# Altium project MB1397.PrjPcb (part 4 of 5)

## Sheet Peripherals.SchDoc: Peripherals
size A4; Date: Not used; ApprovedBy: Not used; CheckedBy: Not used; Author: Not used; CompanyName: STMicroelectronics; DrawnBy: Not used; Engineer: Not used; Organization: Not used; Address1: Not used; Address2: Not used; Address3: Not used; Address4: Not used; DocumentNumber: Not used; Revision: Not used; SheetNumber: 14; SheetTotal: 22
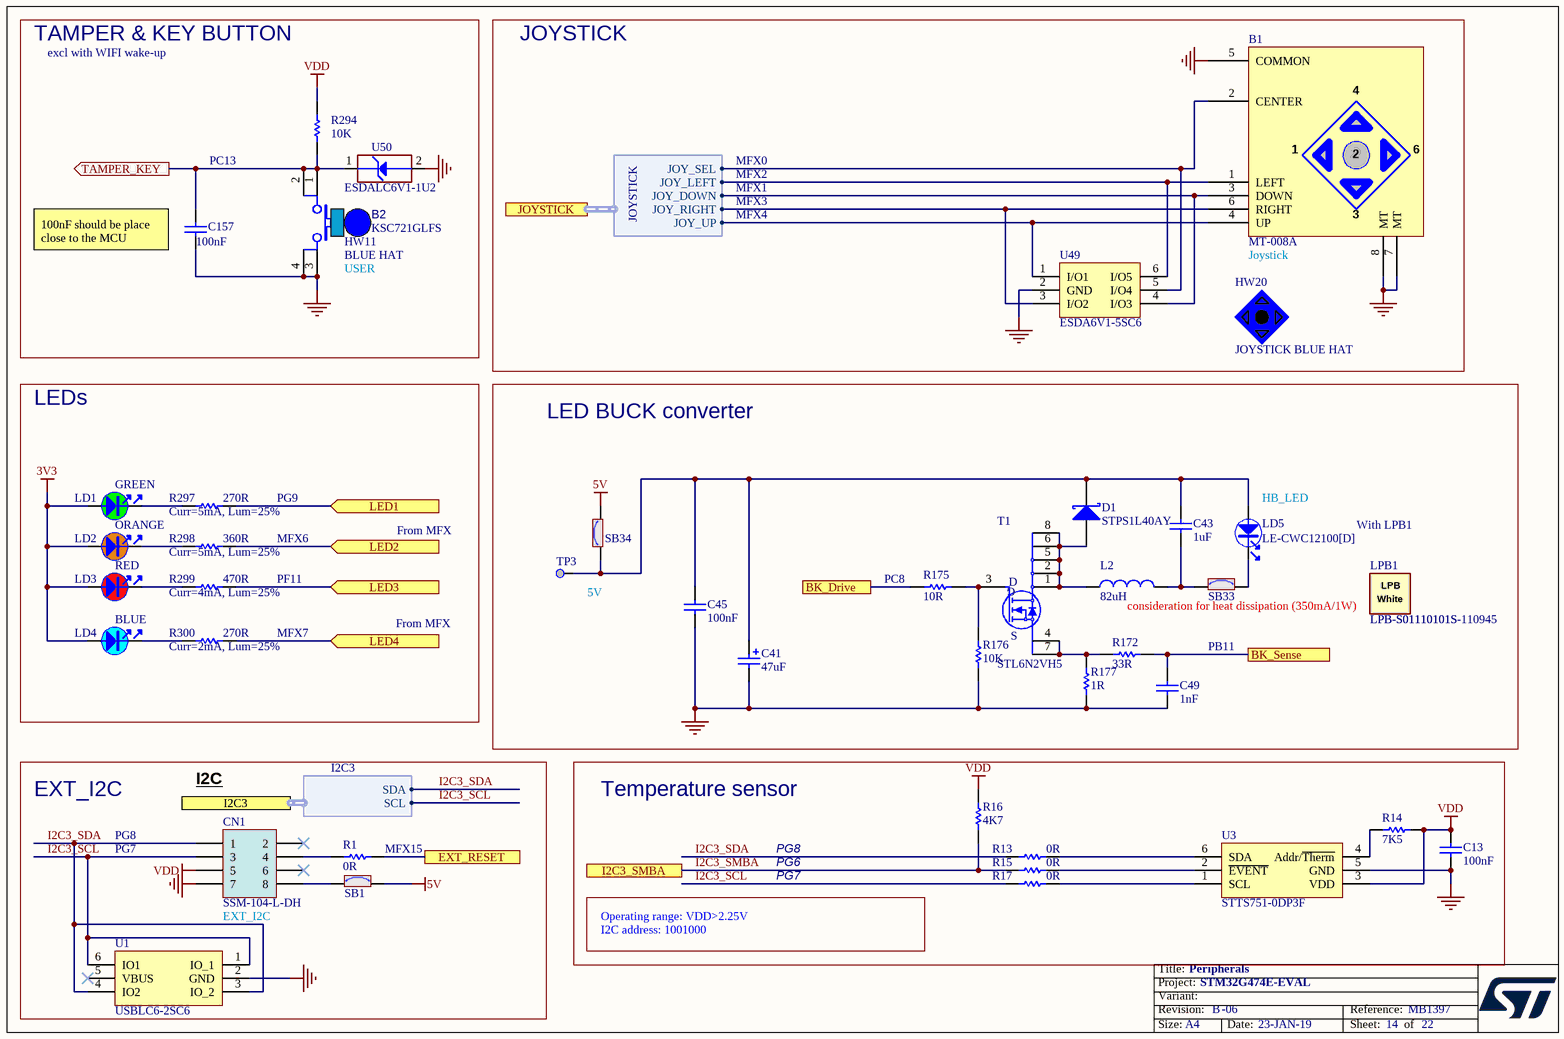
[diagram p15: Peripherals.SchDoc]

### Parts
B1  value MT-008A  [SWI_XIEJIA_MT-008A_6P]  (hidden comment: Joystick MT-008A_M)
B2  value KSC721GLFS  [SWI_C&K_KSC721GLFS_BLUE]  (hidden comment: SW_BLUE_KSC721GLFS)
C13  value 100nF  [C0603]  (hidden comment: Capacitor)
C41  value 47uF  [CPOL_TAJ-C_2312_H2P6]  (hidden comment: Cap_POL_TANA)
C43  value 1uF  [C0603]  (hidden comment: Capacitor)
C45  value 100nF  [C0603]  (hidden comment: Capacitor)
C49  value 1nF  [C0402]  (hidden comment: Capacitor)
C157  value 100nF  [C0402]  (hidden comment: Capacitor)
CN1  value SSM-104-L-DH  [CON_SAMTEC_SSM-104-L-DH]  (hidden comment: Socket 4x2)
D1  value STPS1L40AY  [DIO_SMA_1A_2K]  (hidden comment: SCHOTTKY)
HW11  value BLUE HAT  (hidden comment: BUTTON_HAT_BLUE)  (mechanical)
HW20  value JOYSTICK BLUE HAT  (hidden comment: JOYSTICK_BLUE_HAT)  (mechanical)
L2  value 82uH  [IND_POWER_CYNTEC_PSI054T]  (hidden comment: Inductor)
LD1  value GREEN  [LED_0603_OSRAM_LG-Q396-PS-35_GREEN_1A2K_H0P4]  (hidden comment: LED_green)
LD2  value ORANGE  [LED_0603_OSRAM_LO-Q976-PS-25_ORANGE_1A2K_H0P8]  (hidden comment: LED_orange)
LD3  value RED  [LED_0603_VISHAY_VLMS1300-GS08_RED_1A2K_H0P8]  (hidden comment: LED_red)
LD4  value BLUE  [LED_0603_OSRAM_LB-Q39G-L2OO-35-1_BLUE_1A2K_H0P4]  (hidden comment: LED_blue)
LD5  value LE-CWC12100[D]  [LED_EVERLUCK_CWC12100_WHITE_1A2K]  (hidden comment: LED_white)
LPB1  LPB-S01110101S  value LPB-S01110101S-110945  [LIGHT_10MM-SQUARE-LIGHT-BAR_LUMEX_LPB-S01110101S-110945]
R1  value 0R  [R0402]  (hidden comment: Resistor)
R13  value 0R  [R0603]  (hidden comment: Resistor)
R14  value 7K5  [R0603]  (hidden comment: Resistor)
R15  value 0R  [R0603]  (hidden comment: Resistor)
R16  value 4K7  [R0402]  (hidden comment: Resistor)
R17  value 0R  [R0603]  (hidden comment: Resistor)
R172  value 33R  [R0603]  (hidden comment: Resistor)
R175  value 10R  [R0805]  (hidden comment: Resistor)
R176  value 10K  [R0603]  (hidden comment: Resistor)
R177  value 1R  [R1206_H0P55]  (hidden comment: Resistor)
R294  value 10K  [R0402]  (hidden comment: Resistor)
R297  value 270R  [R0603]  (hidden comment: Resistor)
R298  value 360R  [R0603]  (hidden comment: Resistor)
R299  value 470R  [R0603]  (hidden comment: Resistor)
R300  value 270R  [R0603]  (hidden comment: Resistor)
SB1  SB_ON  [SOLDER-BRIDGE_R0603-0R]  (value not drawn)
SB33  SB_ON  [SOLDER-BRIDGE_R0603-0R]  (value not drawn)
SB34  SB_ON  [SOLDER-BRIDGE_R0603-0R]  (value not drawn)
T1  STL6N2VH5  [MOS_POWERFLAT_2X2_P065]
TP3  Test Point  [TP_SMD_1MM]  (value not drawn)  (no BOM)
U1  USBLC6-2SC6  [ESD_SOT23-6L]
U3  STTS751-0DP3F  [ICC_UDFN6_2X2_P065]
U49  ESDA6V1-5SC6  [ESD_SOT23-6L]
U50  value ESDALC6V1-1U2  [ESD_ST0201]  (hidden comment: ESD-TRANSIL)

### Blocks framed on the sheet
TAMPER & KEY BUTTON: B2 C157 HW11 R294 U50
JOYSTICK: B1 HW20 U49
LEDs: LD1-LD4 R297-R300
LED BUCK converter: C41 C43 C45 C49 D1 L2 LD5 LPB1 R172 R175-R177 SB33 SB34 T1 TP3
EXT_I2C: CN1 R1 SB1 U1
Temperature sensor: C13 R13-R17 U3

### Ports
BK_Drive, BK_Sense, EXT_RESET, I2C3 (harness I2C3), I2C3_SMBA, JOYSTICK (harness JOYSTICK), LED1 (in), LED2 (in), LED3 (in), LED4 (in), TAMPER_KEY (out)

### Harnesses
JOYSTICK: JOY_SEL, JOY_LEFT, JOY_DOWN, JOY_RIGHT, JOY_UP
I2C3: SDA, SCL

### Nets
3V3: LD1.1 LD2.1 LD3.1 LD4.1
5V: SB1.2 SB34.2
GND: B1.5(COMMON) B1.7(MT) B1.8(MT) B2.3 B2.4 C13.2 C41.2 C45.1 C49.1 C157.1 CN1.7 R176.1 R177.1 U1.2(GND) U3.5(GND) U49.2(GND) U50.2(GND)
VDD: C13.1 CN1.5 R14.2 R16.2 R294.2 U3.3(VDD)
BK_Drive: R175.1 ; port BK_Drive
I2C3_SCL: CN1.3 R17.1 U1.1(IO_1) U1.6(IO1) ; port I2C3.SCL
I2C3_SDA: CN1.1 R13.1 U1.3(IO_2) U1.4(IO2) ; port I2C3.SDA
I2C3_SMBA: R15.1 R16.1 ; port I2C3_SMBA
LED1: R297.2 ; port LED1
LED3: R299.2 ; port LED3
MFX_JOY_DOWN: B1.3(DOWN) U49.4(I/O3) ; port JOYSTICK.JOY_DOWN
MFX_JOY_LEFT: B1.1(LEFT) U49.6(I/O5) ; port JOYSTICK.JOY_LEFT
MFX_JOY_RIGHT: B1.6(RIGHT) U49.3(I/O2) ; port JOYSTICK.JOY_RIGHT
MFX_JOY_SEL: B1.2(CENTER) U49.5(I/O4) ; port JOYSTICK.JOY_SEL
MFX_JOY_UP: B1.4(UP) U49.1(I/O1) ; port JOYSTICK.JOY_UP
TAMPER_KEY: B2.1 B2.2 C157.2 R294.1 U50.1(IO1) ; port TAMPER_KEY
NetC41_1: C41.1 C43.2 C45.2 D1.2(K) LD5.1 SB34.1 TP3.1
NetC43_1: C43.1 L2.2 SB33.1
NetC49_2: C49.2 R172.2 ; port BK_Sense
NetCN1_4: CN1.4 R1.1
NetCN1_8: CN1.8 SB1.1
NetD1_1: D1.1(A) L2.1 T1.1(D) T1.2(D) T1.5(D) T1.6(D) T1.8(D)
NetLD1_2: LD1.2 R297.1
NetLD2_2: LD2.2 R298.1
NetLD3_2: LD3.2 R299.1
NetLD4_2: LD4.2 R300.1
NetLD5_2: LD5.2 SB33.2
NetR1_2: R1.2 ; port EXT_RESET
NetR13_2: R13.2 U3.6(SDA)
NetR14_1: R14.1 U3.4(Addr/~{Therm})
NetR15_2: R15.2 U3.2(~{EVENT})
NetR17_2: R17.2 U3.1(SCL)
NetR172_1: R172.1 R177.2 T1.4(S) T1.7(S)
NetR175_2: R175.2 R176.2 T1.3(G)
NetR298_2: R298.2 ; port LED2
NetR300_2: R300.2 ; port LED4

Not connected (* = marked no-connect by the designer): CN1 2* 6*; U1 5(VBUS)*

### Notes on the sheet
- excl with WIFI wake-up
- PC13
- MFX2
- MFX0
- (near C157) 100nF should be place close to the MCU
- MFX1
- MFX3
- MFX4
- (near B2) USER
- (near B1) Joystick
- (near R297) Curr=5mA, Lum=25%
- PG9
- (near LD5) HB_LED
- (near R298) Curr=5mA, Lum=25%
- MFX6
- PF11
- From MFX
- (near R175) PC8
- (near LPB1) With LPB1
- (near R299) Curr=4mA, Lum=25%
- (near R300) Curr=2mA, Lum=25%
- MFX7
- 5V
- consideration for heat dissipation (350mA/1W)
- PB11
- I2C
- PG8
- PG7
- (near R1) MFX15
- EXT_I2C
- Operating range: VDD>2.25V
- PG6
- I2C address: 1001000

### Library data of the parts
B1 = MCD-00132: Joystick, 4 dir, 1 OK; Part_Type: Misc; Manufacturer: XIEJIA Electronics; Provided_By: SUBCO; Initial_Board_Reference: MB1262; Path: ws/MCD_ApplicationBoards/Lists/MCDPARTSdatabase; Item Type: Item
B2 = MCD-00176: Switch HW BLUE High4.3mm 2.25 Newtons; Manufacturer: C&K; Part_Type: Misc; Provided_By: SUBCO; Initial_Board_Reference: MB1274; Path: ws/MCD_ApplicationBoards/Lists/MCDPARTSdatabase; Item Type: Item
C13 C45 = MCD-00211: Capacitor, MLCC, 100nF, 16V, X7R, 10%, 0603, T=0,8mm; Manufacturer_Part_Number: CC0603KRX7R7BB104; Manufacturer: YAGEO; Provided_By: SUBCO; Initial_Board_Reference: MB1319; Path: ws/MCD_ApplicationBoards/Lists/MCDPARTSdatabase; Item Type: Item
C41 = MCD-00559: Capacitor, Tantalum, 47uF, 16V, 10%, TypeC; Manufacturer_Part_Number: TAJC476K016RNJ; Manufacturer: AVX; Provided_By: SUBCO; Initial_Board_Reference: MB1331; Path: ws/MCD_ApplicationBoards/Lists/MCDPARTSdatabase; Item Type: Item
C43 = MCD-00010: Capacitor, MLCC, 1uF, 16V, X5R, 10%, 0603, T=0,8mm; Manufacturer_Part_Number: CC0603KRX5R7BB105; Manufacturer: YAGEO; Provided_By: SUBCO; Initial_Board_Reference: MB1274; Path: ws/MCD_ApplicationBoards/Lists/MCDPARTSdatabase; Item Type: Item
C49 = MCD-00198: Capacitor, MLCC, 1nF, 16V, X7R, 10%, 0402, T=0.5mm; Manufacturer_Part_Number: CC0402KRX7R7BB102; Manufacturer: YAGEO; Provided_By: SUBCO; Initial_Board_Reference: MBxxxx; Path: ws/MCD_ApplicationBoards/Lists/MCDPARTSdatabase; Item Type: Item
C157 = MCD-00006: Capacitor, MLCC, 100nF, 16V, X7R, 10%, 0402, T=0.5mm; Manufacturer_Part_Number: CC0402KRX7R7BB104; Manufacturer: YAGEO; Alternate_Manufacturer_Part_Number: GCM155R71C104KA55D; Alternate_Manufacturer: MURATA; Provided_By: SUBCO; Initial_Board_Reference: MB1274; Path: ws/MCD_ApplicationBoards/Lists/MCDPARTSdatabase; Item Type: Item
CN1 = MCD-00131: Socket, 4x2, 2.54mm, RA, SMT, Height 5.72mm; Manufacturer: SAMTEC; Part_Type: Connector; Provided_By: SUBCO; Initial_Board_Reference: MB1262; Path: ws/MCD_ApplicationBoards/Lists/MCDPARTSdatabase; Item Type: Item
D1 = MCD-00606: Low Drop power Schottky rectifier(1A, 40V, 0.37 V); Part_Type: Diode; Manufacturer: STMICROELECTRONICS; BMS_Part_Number: 9151017; Provided_By: SUBCO with ST control; Initial_Board_Reference: MB1370; Path: ws/MCD_ApplicationBoards/Lists/MCDPARTSdatabase; Item Type: Item
HW11 = MCD-00634: Blue Hat for switch TD0341X-G01-BLU; Part_Type: Mechanical; Manufacturer_Part_Number: 988.16.09.3.00002_SH-517; Manufacturer: JIUBABA; Provided_By: SUBCO; Initial_Board_Reference: MB1319; Path: ws/MCD_ApplicationBoards/Lists/MCDPARTSdatabase; Item Type: Item
HW20 = MCD-01337: Joystick BLue Hat; Part_Type: Mechanical; Manufacturer_Part_Number: KTSC-62-B; Manufacturer: JIUBABA; Provided_By: SUBCO; Initial_Board_Reference: MB1372; Remark: mechanical part only no footprint; Item Type: Item; Path: ws/MCD_ApplicationBoards/Lists/MCDPARTSdatabase
L2 = MCD-03479: Inductor, 82uH, +/-20%, 1A, 0R4, 4.9x4.9mm, T=4mm; Part_Preference: Recommended; Manufacturer: CYNTEC; Manufacturer_Part_Number: SDEI054T-820MS-11; Component_Country_Of_Origin: Unknown; ShowFields: YES; ID: 5595
LD1 = MCD-00588: LED Green, 0603 SMD, Forward Voltage Typ=2V, Max=2.5V; Part_Type: Display; Manufacturer_Part_Number: LG Q396-PS-35; Manufacturer: OSRAM OPTO SEMICONDUCTORS; Alternate_Manufacturer_Part_Number: VLMTG1300-GS08; Alternate_Manufacturer: VISHAY SEMICONDUCTOR OPTO DIVISION; Provided_By: SUBCO; Initial_Board_Reference: MB1331; Path: ws/MCD_ApplicationBoards/Lists/MCDPARTSdatabase; Item Type: Item
LD2 = MCD-00590: LED Orange, 0603 SMD, Forward Voltage Min=1.6V, Max=2.4V; Part_Type: Display; Manufacturer_Part_Number: LO Q976-PS-25; Manufacturer: OSRAM OPTO SEMICONDUCTORS; Alternate_Manufacturer_Part_Number: VLMO1300-GS08; Alternate_Manufacturer: VISHAY SEMICONDUCTOR OPTO DIVISION; Provided_By: SUBCO; Initial_Board_Reference: MB1331; Path: ws/MCD_ApplicationBoards/Lists/MCDPARTSdatabase; Item Type: Item
LD3 = MCD-00587: LED Red, 0603 SMD, 2V Forward Voltage; Part_Type: Display; Manufacturer_Part_Number: VLMS1300-GS08; Manufacturer: VISHAY; Alternate_Manufacturer_Part_Number: LS Q976-NR-1; Alternate_Manufacturer: OSRAM OPTO SEMICONDUCTORS; Provided_By: SUBCO; Initial_Board_Reference: MB1331; Path: ws/MCD_ApplicationBoards/Lists/MCDPARTSdatabase; Item Type: Item
LD4 = MCD-00585: LED Blue, 0603 SMD, Forward Voltage Min=2,8V, Max=3,8V; Part_Type: Display; Manufacturer_Part_Number: LB Q39G-L2OO-35-1; Manufacturer: OSRAM OPTO SEMICONDUCTORS; Order_Code_RS: 9148643; Provided_By: SUBCO; Initial_Board_Reference: MB1331; Path: ws/MCD_ApplicationBoards/Lists/MCDPARTSdatabase; Item Type: Item
LD5 = MCD-01186: White SMD LED lamp, Forward Voltage Typ=2.8V, Max=3.6V; Part_Type: Display; Manufacturer: EVERLUCK; Provided_By: SUBCO; Initial_Board_Reference: MB1397; Path: ws/MCD_ApplicationBoards/Lists/MCDPARTSdatabase; Item Type: Item
LPB1 = MCD-01191: 10mm Square Light Bar.; Part_Type: Misc; Manufacturer: LUMEX; Provided_By: SUBCO; Initial_Board_Reference: MB1397; Remark: LED pad removed. Please validat.; Path: ws/MCD_ApplicationBoards/Lists/MCDPARTSdatabase; Item Type: Item
R1 = MCD-00052: Resistor,0R,0402,5%,1/16W; Manufacturer_Part_Number: RC0402JR-070RL; Manufacturer: YAGEO; Provided_By: SUBCO; Initial_Board_Reference: MB1274; Path: ws/MCD_ApplicationBoards/Lists/MCDPARTSdatabase; Item Type: Item
R13 R15 R17 = MCD-00056: Resistor,0R,0603,5%,1/10W; Manufacturer_Part_Number: RC0603JR-070RL; Manufacturer: YAGEO; Provided_By: SUBCO; Initial_Board_Reference: MB1274; Path: ws/MCD_ApplicationBoards/Lists/MCDPARTSdatabase; Item Type: Item
R14 = MCD-00520: Resistor,7K5,0603,1%,1/10W; Manufacturer_Part_Number: RC0603FR-077K5L; Manufacturer: YAGEO; Provided_By: SUBCO; Initial_Board_Reference: MBxxxx; Path: ws/MCD_ApplicationBoards/Lists/MCDPARTSdatabase; Item Type: Item
R16 = MCD-00065: Resistor,4K7,0402,1%,1/16W; Manufacturer_Part_Number: RC0402FR-074K7L; Manufacturer: YAGEO; Alternate_Manufacturer_Part_Number: RT0402FRE074K7L; Provided_By: SUBCO; Initial_Board_Reference: MB1274; Path: ws/MCD_ApplicationBoards/Lists/MCDPARTSdatabase; Item Type: Item
R172 = MCD-00456: Resistor,33R,0603,1%,1/10W; Manufacturer_Part_Number: RC0603FR-0733RL; Manufacturer: YAGEO; BMS_Part_Number: 9129732; Provided_By: SUBCO; Initial_Board_Reference: MBxxxx; Path: ws/MCD_ApplicationBoards/Lists/MCDPARTSdatabase; Item Type: Item
R175 = MCD-01111: Resistor,10R,0805,1%,Stackpole,1/4W; Manufacturer_Part_Number: RNCP0805FTD10R0; Provided_By: SUBCO; Initial_Board_Reference: MB1381; Path: ws/MCD_ApplicationBoards/Lists/MCDPARTSdatabase; Item Type: Item
R176 = MCD-00220: Resistor,10K,0603,1%,1/10W; Manufacturer_Part_Number: RC0603FR-0710KL; Manufacturer: YAGEO; Provided_By: SUBCO; Initial_Board_Reference: MB1319; Path: ws/MCD_ApplicationBoards/Lists/MCDPARTSdatabase; Item Type: Item
R177 = MCD-01185: Resistor, 1R, 1206, 1%, 1/4W; Manufacturer_Part_Number: CRCW12061R00FKEA; Manufacturer: VISHAY; Provided_By: SUBCO; Initial_Board_Reference: MB1397; Remark: update footprint name; Path: ws/MCD_ApplicationBoards/Lists/MCDPARTSdatabase; Item Type: Item
R294 = MCD-00053: Resistor,10K,0402,1%,1/16W; Manufacturer_Part_Number: RC0402FR-0710KL; Manufacturer: YAGEO; Provided_By: SUBCO; Initial_Board_Reference: MB1274; Path: ws/MCD_ApplicationBoards/Lists/MCDPARTSdatabase; Item Type: Item
R297 R300 = MCD-00442: Resistor,270R,0603,1%,1/10W; Manufacturer_Part_Number: RC0603FR-07270RL; Manufacturer: YAGEO; Provided_By: SUBCO; Initial_Board_Reference: MBxxxx; Path: ws/MCD_ApplicationBoards/Lists/MCDPARTSdatabase; Item Type: Item
R298 = MCD-00462: Resistor,360R,0603,1%,1/10W; Manufacturer_Part_Number: RC0603FR-07360RL; Manufacturer: YAGEO; BMS_Part_Number: 9129744; Provided_By: SUBCO; Initial_Board_Reference: MBxxxx; Path: ws/MCD_ApplicationBoards/Lists/MCDPARTSdatabase; Item Type: Item
R299 = MCD-00354: Resistor,470R,0603,1%,1/10W; Manufacturer_Part_Number: RC0603FR-07470RL; Manufacturer: YAGEO; BMS_Part_Number: 9129906; Provided_By: SUBCO; Initial_Board_Reference: MBxxxx; Path: ws/MCD_ApplicationBoards/Lists/MCDPARTSdatabase; Item Type: Item
SB1 SB33 SB34 = MCD-00071: Solder Bridge ON; Part_Type: Mechanical; Manufacturer_Part_Number: RC0603JR-070RL; Manufacturer: YAGEO; Provided_By: SUBCO; Initial_Board_Reference: MB1274; Path: ws/MCD_ApplicationBoards/Lists/MCDPARTSdatabase; Item Type: Item
T1 = MCD-01028: N-channel 20 V, 0.025 O typ., 6 A STripFET™ V Power MOSFET in a PowerFLAT™ 2x2 package; Part_Type: IC; Manufacturer: STMICROELECTRONICS; BMS_Part_Number: 9153558; Provided_By: SUBCO with ST control; Initial_Board_Reference: MB1378; Remark: Update with official footprint according to layout rules; Path: ws/MCD_ApplicationBoards/Lists/MCDPARTSdatabase; Item Type: Item
TP3 = MCD-00074: Test Point 1mm; Part_Type: Mechanical; Initial_Board_Reference: MB1274; Path: ws/MCD_ApplicationBoards/Lists/MCDPARTSdatabase; Item Type: Item
U1 = MCD-00163: Very low capacitance ESD protection; Part_Type: IC; Manufacturer: STMICROELECTRONICS; BMS_Part_Number: 9151075; Provided_By: SUBCO with ST control; Initial_Board_Reference: MB1263; Path: ws/MCD_ApplicationBoards/Lists/MCDPARTSdatabase; Item Type: Item
U3 = MCD-01551: IC, 2.25 V low-voltage local digital temperature sensor, UDFN-6L; Manufacturer: STMICROELECTRONICS; Provided_By: SUBCO with ST control; Initial_Board_Reference: MB1397; Path: ws/MCD_ApplicationBoards/Lists/MCDPARTSdatabase; Item Type: Item
U49 = MCD-01066: 5 unidirectional Transil diodes ESD protection; Part_Type: Diode; Manufacturer: STMICROELECTRONICS; BMS_Part_Number: 9179044; Provided_By: SUBCO with ST control; Initial_Board_Reference: MB1331; Path: ws/MCD_ApplicationBoards/Lists/MCDPARTSdatabase; Item Type: Item
U50 = MCD-00170: ESD protection 6V1; Part_Type: Diode; Manufacturer: STMICROELECTRONICS; BMS_Part_Number: 9151132; Provided_By: SUBCO with ST control; Initial_Board_Reference: MB1274; Path: ws/MCD_ApplicationBoards/Lists/MCDPARTSdatabase; Item Type: Item

## Sheet STLink_V3E_SWD.SchDoc: ST-LINK V3 SWD Module
size A3; Date: Not used; ApprovedBy: Not used; CheckedBy: Not used; Author: Not used; CompanyName: STMicroelectronics; DrawnBy: Not used; Engineer: Not used; Organization: Not used; Address1: Not used; Address2: Not used; Address3: Not used; Address4: Not used; DocumentNumber: Not used; Revision: Not used; SheetNumber: 21; SheetTotal: 22
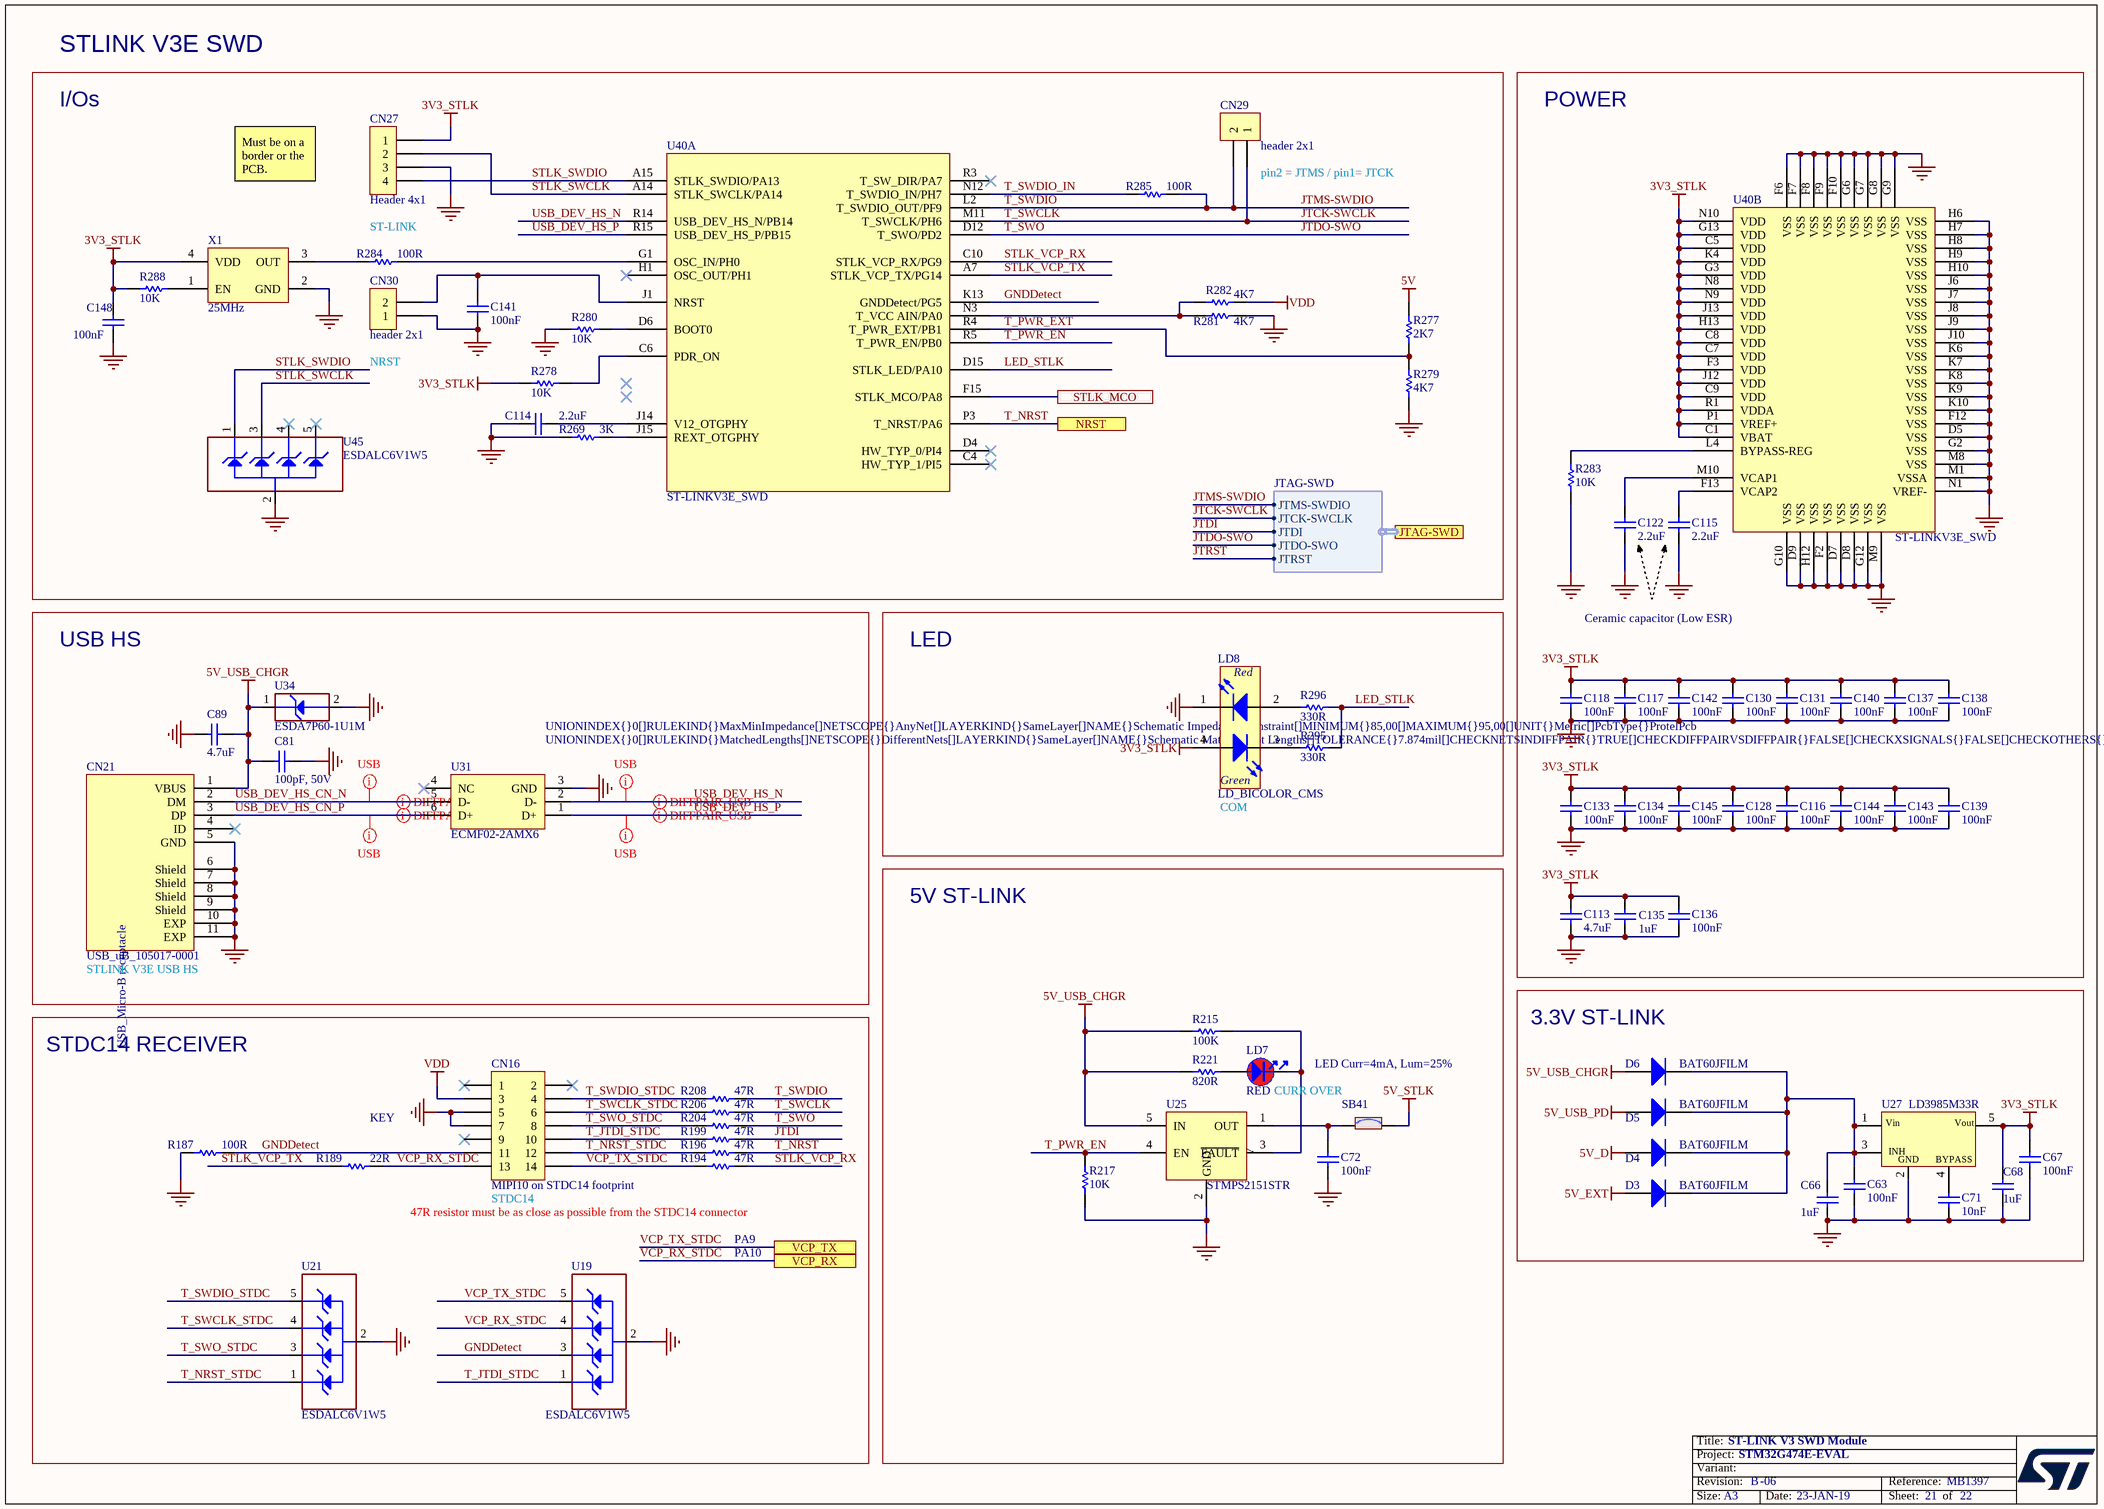
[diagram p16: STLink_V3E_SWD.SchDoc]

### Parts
C63  value 100nF  [C0402]  (hidden comment: Capacitor)
C66  value 1uF  [C0603]  (hidden comment: Capacitor)
C67  value 100nF  [C0603]  (hidden comment: Capacitor)
C68  value 1uF  [C0603]  (hidden comment: Capacitor)
C71  value 10nF  [C0402]  (hidden comment: Capacitor)
C72  value 100nF  [C0402]  (hidden comment: Capacitor)
C81  value 100pF, 50V  [C0603]  (hidden comment: Capacitor)
C89  value 4.7uF  [C0603]  (hidden comment: Capacitor)
C113  value 4.7uF  [C0603]  (hidden comment: Capacitor)
C114  value 2.2uF  [C0603]  (hidden comment: Capacitor)
C115  value 2.2uF  [C1206_H1P15]  (hidden comment: Capacitor)
C116  value 100nF  [C0402]  (hidden comment: Capacitor)
C117  value 100nF  [C0402]  (hidden comment: Capacitor)
C118  value 100nF  [C0402]  (hidden comment: Capacitor)
C122  value 2.2uF  [C1206_H1P15]  (hidden comment: Capacitor)
C128  value 100nF  [C0402]  (hidden comment: Capacitor)
C130  value 100nF  [C0402]  (hidden comment: Capacitor)
C131  value 100nF  [C0402]  (hidden comment: Capacitor)
C133  value 100nF  [C0402]  (hidden comment: Capacitor)
C134  value 100nF  [C0402]  (hidden comment: Capacitor)
C135  value 1uF  [C0603]  (hidden comment: Capacitor)
C136  value 100nF  [C0402]  (hidden comment: Capacitor)
C137  value 100nF  [C0402]  (hidden comment: Capacitor)
C138  value 100nF  [C0402]  (hidden comment: Capacitor)
C139  value 100nF  [C0402]  (hidden comment: Capacitor)
C140  value 100nF  [C0402]  (hidden comment: Capacitor)
C141  value 100nF  [C0402]  (hidden comment: Capacitor)
C142  value 100nF  [C0402]  (hidden comment: Capacitor)
C143  value 100nF  [C0402]  (hidden comment: Capacitor)
C144  value 100nF  [C0402]  (hidden comment: Capacitor)
C145  value 100nF  [C0402]  (hidden comment: Capacitor)
C148  value 100nF  [C0402]  (hidden comment: Capacitor)
CN16  value MIPI10 on STDC14 footprint  [CON_STDC14_Receiver_MEDIUM_WITH_MIPI10_3D]  (hidden comment: Header 7x2)
CN21  value USB_uB_105017-0001  [CON_USBMICROB_MOLEX_105017-0001_H2P90]  (hidden comment: USB_uB_105017.0001)
CN27  Header 4x1  [CON_SAMTEC_TSW-104-07-G-S]
CN29  Header 2x1  [CON_988-JIUBABA_PHFS25-11-02-G0B115-T-1]
CN30  Header 2x1  [CON_988-JIUBABA_PHFS25-11-02-G0B115-T-1]
D3  BAT60JFILM  [DIO_SOD323]
D4  BAT60JFILM  [DIO_SOD323]
D5  BAT60JFILM  [DIO_SOD323]
D6  BAT60JFILM  [DIO_SOD323]
LD7  value RED  [LED_0603_VISHAY_VLMS1300-GS08_RED_1A2K_H0P8]  (hidden comment: LED_red)
LD8  LD_BICOLOR_CMS  [LED_BI-GR_HSMF-A201-A00J1]
R187  value 100R  [R0402]  (hidden comment: Resistor)
R189  value 22R  [R0402]  (hidden comment: Resistor)
R194  value 47R  [R0402]  (hidden comment: Resistor)
R196  value 47R  [R0402]  (hidden comment: Resistor)
R199  value 47R  [R0402]  (hidden comment: Resistor)
R204  value 47R  [R0402]  (hidden comment: Resistor)
R206  value 47R  [R0402]  (hidden comment: Resistor)
R208  value 47R  [R0402]  (hidden comment: Resistor)
R215  value 100K  [R0603]  (hidden comment: Resistor)
R217  value 10K  [R0402]  (hidden comment: Resistor)
R221  value 820R  [R0402]  (hidden comment: Resistor)
R269  value 3K  [R0402]  (hidden comment: Resistor)
R277  value 2K7  [R0402]  (hidden comment: Resistor)
R278  value 10K  [R0402]  (hidden comment: Resistor)
R279  value 4K7  [R0402]  (hidden comment: Resistor)
R280  value 10K  [R0402]  (hidden comment: Resistor)
R281  value 4K7  [R0402]  (hidden comment: Resistor)
R282  value 4K7  [R0402]  (hidden comment: Resistor)
R283  value 10K  [R0402]  (hidden comment: Resistor)
R284  value 100R  [R0402]  (hidden comment: Resistor)
R285  value 100R  [R0402]  (hidden comment: Resistor)
R288  value 10K  [R0402]  (hidden comment: Resistor)
R295  value 330R  [R0603]  (hidden comment: Resistor)
R296  value 330R  [R0603]  (hidden comment: Resistor)
SB41  SB_ON  [SOLDER-BRIDGE_R0603-0R]  (value not drawn)
U19  ESDALC6V1W5  [ESD_SOT323-5L]
U21  ESDALC6V1W5  [ESD_SOT323-5L]
U25  STMPS2151STR  [MOS_SOT23-5L]
U27  LD3985M33R  [REG_SOT23-5L]
U31  ECMF02-2AMX6  [ESD_QFN-6L_1P7X1P5_P050]
U34  value ESDA7P60-1U1M  [ESD_QFN2_1P6X1_P125]  (hidden comment: ESD-TRANSIL)
U40  ST-LINKV3E_SWD  [ICC_UFBGA201_176+25_10X10_P065]  (parts A,B of 2)
U45  ESDALC6V1W5  [ESD_SOT323-5L]
X1  value 25MHz  [OSC_NDK_NZ2520SB_4P]  (hidden comment: OSCILLATOR_4_PINS)

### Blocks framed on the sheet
STLINK V3E SWD: C114 C141 C148 CN27 CN29 CN30 R269 R277-R282 R284 R285 R288 U40 U45 X1
POWER: C113 C115-C118 C122 C128 C130 C131 C133-C140 C142-C145 R283 U40
USB HS: C81 C89 CN21 U31 U34
LED: LD8 R295 R296
5V ST-LINK: C72 LD7 R215 R217 R221 SB41 U25
3.3V ST-LINK: C63 C66-C68 C71 D3-D6 U27
STDC14 RECEIVER: CN16 R187 R189 R194 R196 R199 R204 R206 R208 U19 U21

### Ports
JTAG-SWD (harness JTAG-SWD), NRST, STLK_MCO, VCP_RX, VCP_TX

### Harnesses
JTAG-SWD: JTMS-SWDIO, JTCK-SWCLK, JTDI, JTDO-SWO, JTRST

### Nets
3V3_STLK: C67.2 C68.2 C113.2 C116.2 C117.2 C118.2 C128.2 C130.2 C131.2 C133.2 C134.2 C135.2 C136.2 C137.2 C138.2 C139.2 C140.2 C142.2 C143.2 C144.2 C145.2 C148.2 CN27.1 LD8.4(YellowGreen_anode) R278.1 R288.1 U27.5(Vout) U40.C1(VBAT) U40.C5(VDD) U40.C7(VDD) U40.C8(VDD) U40.C9(VDD) U40.F3(VDD) U40.G3(VDD) U40.G13(VDD) U40.H13(VDD) U40.J12(VDD) U40.J13(VDD) U40.K4(VDD) U40.N8(VDD) U40.N9(VDD) U40.N10(VDD) U40.P1(VREF+) U40.R1(VDDA) X1.4(VDD)
5V: R277.2
5V_D: D4.1(A)
5V_EXT: D3.1(A)
5V_STLK: SB41.2
5V_USB_CHGR: C81.1 C89.2 CN21.1(VBUS) D6.1(A) R215.1 R221.1 U25.5(IN) U34.1(IO1)
5V_USB_PD: D5.1(A)
GND: C63.1 C66.2 C67.1 C68.1 C71.1 C72.1 C81.2 C89.1 C113.1 C114.1 C115.1 C116.1 C117.1 C118.1 C122.1 C128.1 C130.1 C131.1 C133.1 C134.1 C135.1 C136.1 C137.1 C138.1 C139.1 C140.1 C141.1 C142.1 C143.1 C144.1 C145.1 C148.1 CN16.5 CN16.7 CN21.5(GND) CN21.6(Shield) CN21.7(Shield) CN21.8(Shield) CN21.9(Shield) CN21.10(EXP) CN21.11(EXP) CN27.3 CN30.1 LD8.1(RED_cathode) R187.1 R217.1 R269.1 R279.1 R280.1 R281.2 R283.1 U19.2(GND) U21.2(GND) U25.2(GND) U27.2(GND) U31.3(GND) U34.2(GND) U40.D5(VSS) U40.D7(VSS) U40.D8(VSS) U40.D9(VSS) U40.F2(VSS) U40.F6(VSS) U40.F7(VSS) U40.F8(VSS) U40.F9(VSS) U40.F10(VSS) U40.F12(VSS) U40.G2(VSS) U40.G6(VSS) U40.G7(VSS) U40.G8(VSS) U40.G9(VSS) U40.G10(VSS) U40.G12(VSS) U40.H6(VSS) U40.H7(VSS) U40.H8(VSS) U40.H9(VSS) U40.H10(VSS) U40.H12(VSS) U40.J6(VSS) U40.J7(VSS) U40.J8(VSS) U40.J9(VSS) U40.J10(VSS) U40.K6(VSS) U40.K7(VSS) U40.K8(VSS) U40.K9(VSS) U40.K10(VSS) U40.M1(VSSA) U40.M8(VSS) U40.M9(VSS) U40.N1(VREF-) U45.2(GND) X1.2(GND)
VDD: CN16.3 R282.2
GNDDetect: CN16.11 R187.2 U19.3(IO2) U40.K13(GNDDetect/PG5)
JTCK-SWCLK: CN29.1 R206.2 U40.M11(T_SWCLK/PH6) ; port JTAG-SWD.JTCK-SWCLK  [also labelled T_SWCLK]
JTDI: R199.2 ; port JTAG-SWD.JTDI
JTDO-SWO: R204.2 U40.D12(T_SWO/PD2) ; port JTAG-SWD.JTDO-SWO  [also labelled T_SWO]
JTMS-SWDIO: CN29.2 R208.2 R285.2 U40.L2(T_SWDIO_OUT/PF9) ; port JTAG-SWD.JTMS-SWDIO  [also labelled T_SWDIO]
LED_STLK: R295.2 R296.2 U40.D15(STLK_LED/PA10)
STLK_SWCLK: CN27.2 U40.A14(STLK_SWCLK/PA14) U45.3(IO2)
STLK_SWDIO: CN27.4 U40.A15(STLK_SWDIO/PA13) U45.1(IO1)
STLK_VCP_RX: R194.2 U40.C10(STLK_VCP_RX/PG9)
STLK_VCP_TX: R189.1 U40.A7(STLK_VCP_TX/PG14)
T_JTDI_STDC: CN16.10 R199.1 U19.1(IO1)
T_NRST: R196.2 U40.P3(T_NRST/PA6) ; port NRST  [project net NRST]
T_NRST_STDC: CN16.12 R196.1 U21.1(IO1)
T_PWR_EN: R217.2 U25.4(EN) U40.R5(T_PWR_EN/PB0)
T_PWR_EXT: R277.1 R279.2 U40.R4(T_PWR_EXT/PB1)
T_SWCLK_STDC: CN16.6 R206.1 U21.4(IO3)
T_SWDIO_IN: R285.1 U40.N12(T_SWDIO_IN/PH7)
T_SWDIO_STDC: CN16.4 R208.1 U21.5(IO4)
T_SWO_STDC: CN16.8 R204.1 U21.3(IO2)
USB_DEV_HS_CN_N: CN21.2(DM) U31.5(D-)
USB_DEV_HS_CN_P: CN21.3(DP) U31.6(D+)
USB_DEV_HS_N: U31.2(D-) U40.R14(USB_DEV_HS_N/PB14)
USB_DEV_HS_P: U31.1(D+) U40.R15(USB_DEV_HS_P/PB15)
VCP_RX_STDC: CN16.13 R189.2 U19.4(IO3) ; port VCP_RX
VCP_TX_STDC: CN16.14 R194.1 U19.5(IO4) ; port VCP_TX
NetC63_2: C63.2 C66.1 D3.2(K) D4.2(K) D5.2(K) D6.2(K) U27.1(Vin) U27.3(CE)
NetC71_2: C71.2 U27.4(BYPASS)
NetC72_2: C72.2 SB41.1 U25.1(OUT)
NetC114_2: C114.2 U40.J14(V12_OTGPHY)
NetC115_2: C115.2 U40.F13(VCAP2)
NetC122_2: C122.2 U40.M10(VCAP1)
NetC141_2: C141.2 CN30.2 U40.J1(NRST)
NetLD7_1: LD7.1 R221.2
NetLD7_2: LD7.2 R215.2 U25.3(~{FAULT})
NetLD8_2: LD8.2(Red_anode) R296.1
NetLD8_3: LD8.3(YellowGreen_cathode) R295.1
NetR269_2: R269.2 U40.J15(REXT_OTGPHY)
NetR278_2: R278.2 U40.C6(PDR_ON)
NetR280_2: R280.2 U40.D6(BOOT0)
NetR281_1: R281.1 R282.1 U40.N3(T_VCC_AIN/PA0)
NetR283_2: R283.2 U40.L4(BYPASS-REG)
NetR284_1: R284.1 X1.3(OUT)
NetR284_2: R284.2 U40.G1(OSC_IN/PH0)
NetR288_2: R288.2 X1.1(EN)
NetR312_1: U40.F15(STLK_MCO/PA8) ; port STLK_MCO

Not connected (* = marked no-connect by the designer): CN16 1* 2* 9*; CN21 4(ID)*; U31 4(NC)*; U40 C4(HW_TYP_1/PI5)* D4(HW_TYP_0/PI4)* H1(OSC_OUT/PH1)* R3(T_SW_DIR/PA7)*; U45 4(IO3)* 5(IO4)*

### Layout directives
differential pair; rule Impedance Constraint [Min = 85.00    Max = 95.00    ]: USB_DEV_HS_CN_N, USB_DEV_HS_CN_P, USB_DEV_HS_N, USB_DEV_HS_P
rule Undefined; rule Matched Net Lengths [Tolerance = 0.2mm]; rule Impedance Constraint [Min = 85.00    Max = 95.00    ]: USB_DEV_HS_CN_N, USB_DEV_HS_CN_P, USB_DEV_HS_N, USB_DEV_HS_P

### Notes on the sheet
- I/Os
- Must be on a border or the PCB.
- (near CN29) pin2 = JTMS / pin1= JTCK
- ST-LINK
- (near CN30) NRST
- Ceramic capacitor (Low ESR)
- COM
- (near CN21) STLINK V3E USB HS
- (near R189) KEY
- (near LD7) CURR OVER
- LED Curr=4mA, Lum=25%
- 47R resistor must be as close as possible from the STDC14 connector
- (near CN16) STDC14
- PA9
- PA10

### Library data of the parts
C63 C72 C116-C118 C128 C130 C131 C133 C134 C136-C145 C148 = MCD-00006: as C157 on sheet Peripherals
C66 C68 C135 = MCD-00010: as C43 on sheet Peripherals
C67 = MCD-00211: as C13 on sheet Peripherals
C71 = MCD-00011: Capacitor, MLCC, 10nF, 16V, X7R, 10%, 0402, T=0.5mm; Manufacturer_Part_Number: CC0402KRX7R7BB103; Manufacturer: YAGEO; Provided_By: SUBCO; Initial_Board_Reference: MB1274; Path: ws/MCD_ApplicationBoards/Lists/MCDPARTSdatabase; Item Type: Item
C81 = MCD-01101: Capacitor,100pF,50V,X7R,10%,0603; Manufacturer_Part_Number: 06035C101JAT4A; Manufacturer: AVX; Provided_By: SUBCO; Initial_Board_Reference: MB1381; Path: ws/MCD_ApplicationBoards/Lists/MCDPARTSdatabase; Item Type: Item
C89 C113 = MCD-00009: Capacitor, MLCC, 4.7uF, 16V, X5R, 10%, 0603, T=0.8mm; Manufacturer_Part_Number: CC0603KRX5R7BB475; Manufacturer: YAGEO; Provided_By: SUBCO; Initial_Board_Reference: MB1274; Path: ws/MCD_ApplicationBoards/Lists/MCDPARTSdatabase; Item Type: Item
C114 = MCD-00012: Capacitor, MLCC, 2.2uF, 10V, X5R, 10%, 0603, T=0,8mm; Manufacturer_Part_Number: CC0603KRX5R6BB225; Manufacturer: YAGEO; Alternate_Manufacturer_Part_Number: C0603C225K8PACTU; Alternate_Manufacturer: KEMET; Provided_By: SUBCO; Initial_Board_Reference: MB1274; Path: ws/MCD_ApplicationBoards/Lists/MCDPARTSdatabase; Item Type: Item
C115 C122 = MCD-00008: Capacitor, MLCC, 2.2uF, 16V, X7R, 10%, 1206, T=1,15mm; Manufacturer_Part_Number: CC1206KKX7R7BB225; Manufacturer: YAGEO; Alternate_Manufacturer_Part_Number: C1206C225K4RAC; Alternate_Manufacturer: KEMET; Provided_By: SUBCO; Initial_Board_Reference: MB1274; Path: ws/MCD_ApplicationBoards/Lists/MCDPARTSdatabase; Item Type: Item
CN16 = MCD-01226: Header 5x2, 1.27mm, Dual row, Straight, Surface mount, vertical male connector. 3.05mm lead. Mates with FFSD connector. Footprint compatible with FTSH-107-01-L-DV,-K,-A,-P,-ES (STDC14 MEDIUM); Manufacturer_Part_Number: FTSH-105-01-L-DV-K; Manufacturer: SAMTEC; Provided_By: SUBCO; Initial_Board_Reference: MCD16-052; Path: ws/MCD_ApplicationBoards/Lists/MCDPARTSdatabase; Item Type: Item
CN21 = MCD-00028: USB-MICRO-B, 0.65mm, RA, SMT, Bottom Mount,; Manufacturer_Part_Number: 1050170001; Manufacturer: MOLEX; Part_Type: Connector; Provided_By: SUBCO; Initial_Board_Reference: MB1274; Path: ws/MCD_ApplicationBoards/Lists/MCDPARTSdatabase; Item Type: Item
CN27 = MCD-00029: Header, 4x1, 2,54mm, VR, TH, Height 5.84mm/2.54mm; Manufacturer_Part_Number: TSW-104-07-x-S; Manufacturer: SAMTEC; Part_Type: Connector; Provided_By: SUBCO; Initial_Board_Reference: MB1274; Path: ws/MCD_ApplicationBoards/Lists/MCDPARTSdatabase; Item Type: Item
CN29 CN30 = MCD-00314: Header, 2x1, 2.54mm, VR, TH, Height 6mm/3mm; Part_Type: Connector; Manufacturer_Part_Number: PHFS25-11-02-G0B115-T-1; Manufacturer: JIUBABA; Provided_By: SUBCO; Initial_Board_Reference: MB1311; Path: ws/MCD_ApplicationBoards/Lists/MCDPARTSdatabase; Item Type: Item
D3-D6 = MCD-00034: Manufacturer: STMICROELECTRONICS; Part_Type: Diode; BMS_Part_Number: 9151097; Provided_By: SUBCO with ST control; Initial_Board_Reference: MB1274; Path: ws/MCD_ApplicationBoards/Lists/MCDPARTSdatabase; Item Type: Item
LD7 = MCD-00587: as LD3 on sheet Peripherals
LD8 = MCD-00051: LED Bicolor; Part_Type: Display; Manufacturer_Part_Number: HSMF-A201-A00J1; Manufacturer: AVAGO TECHNOLOGIES; Alternate_Manufacturer_Part_Number: LE-RGW35280; Alternate_Manufacturer: EVERLUCK; Provided_By: SUBCO; Initial_Board_Reference: MB1274; Path: ws/MCD_ApplicationBoards/Lists/MCDPARTSdatabase; Item Type: Item
R187 R284 R285 = MCD-00067: Resistor, 100R, 0402, +/- 1%, 1/16W; Manufacturer_Part_Number: RC0402FR-07100RL; Manufacturer: YAGEO; Part_Preference: Recommended; Order_Code_RS: 9239111; Component_Country_Of_Origin: China; ShowFields: YES; ID: 2527
R189 = MCD-00189: Resistor,22R,0402,1%,1/16W; Manufacturer_Part_Number: RC0402FR-0722RL; Manufacturer: YAGEO; Provided_By: SUBCO; Initial_Board_Reference: MBxxxx; Path: ws/MCD_ApplicationBoards/Lists/MCDPARTSdatabase; Item Type: Item
R194 R196 R199 R204 R206 R208 = MCD-00481: Resistor,47R,0402,1%,1/16W
R215 = MCD-00223: Resistor,100K,0603,1%,1/10W; Manufacturer_Part_Number: RC0603FR-07100KL; Manufacturer: YAGEO; Provided_By: SUBCO; Initial_Board_Reference: MB1319; Path: ws/MCD_ApplicationBoards/Lists/MCDPARTSdatabase; Item Type: Item
R217 R278 R280 R283 R288 = MCD-00053: as R294 on sheet Peripherals
R221 = MCD-00527: Resistor,820R,0402,1%,1/16W; Manufacturer_Part_Number: RC0402FR-07820RL; Manufacturer: YAGEO; Provided_By: SUBCO; Initial_Board_Reference: MBxxxx; Path: ws/MCD_ApplicationBoards/Lists/MCDPARTSdatabase; Item Type: Item
R269 = MCD-00185: Resistor,3K,0402,1%,1/16W; Manufacturer_Part_Number: RC0402FR-073KL; Manufacturer: YAGEO; Provided_By: SUBCO; Initial_Board_Reference: MBxxxx; Path: ws/MCD_ApplicationBoards/Lists/MCDPARTSdatabase; Item Type: Item
R277 = MCD-00055: Resistor,2K7,0402,1%,1/16W; Manufacturer_Part_Number: RC0402FR-072K7L; Manufacturer: YAGEO; Provided_By: SUBCO; Initial_Board_Reference: MB1274; Path: ws/MCD_ApplicationBoards/Lists/MCDPARTSdatabase; Item Type: Item
R279 R281 R282 = MCD-00065: as R16 on sheet Peripherals
R295 R296 = MCD-00197: Resistor,330R,0603,1%,1/10W; Manufacturer_Part_Number: RC0603FR-07330RL; Manufacturer: YAGEO; BMS_Part_Number: 9129729; Provided_By: SUBCO; Initial_Board_Reference: MBxxxx; Path: ws/MCD_ApplicationBoards/Lists/MCDPARTSdatabase; Item Type: Item
SB41 = MCD-00071: as SB1 on sheet Peripherals
U19 U21 = MCD-00136: Dual Transil array for ESD protection; Part_Type: Diode; Manufacturer: STMICROELECTRONICS; BMS_Part_Number: 9151112; Provided_By: SUBCO with ST control; Initial_Board_Reference: MB1262; Path: ws/MCD_ApplicationBoards/Lists/MCDPARTSdatabase; Item Type: Item
U25 = MCD-00159: 500mA, Enhanced single channel power switches with active high enable pin; Part_Type: IC; Manufacturer: STMICROELECTRONICS; Alternate_Manufacturer_Part_Number: TPS2051C; Alternate_Manufacturer: TEXAS INSTRUMENTS; BMS_Part_Number: 9159009; Provided_By: SUBCO with ST control; Initial_Board_Reference: MB1264; Path: ws/MCD_ApplicationBoards/Lists/MCDPARTSdatabase; Item Type: Item
U27 = MCD-00086: Ultra low drop-low noise BiCMOS voltage, regulators low ESR capacitors compatible; Manufacturer: STMICROELECTRONICS; Part_Type: IC; BMS_Part_Number: 9176161; Provided_By: SUBCO with ST control; Initial_Board_Reference: MB1274; Path: ws/MCD_ApplicationBoards/Lists/MCDPARTSdatabase; Item Type: Item
U31 = MCD-00649: Common mode filter with ESD protection for USB 2.0 interface; Part_Type: Diode; Manufacturer: STMICROELECTRONICS; BMS_Part_Number: 9151138; Provided_By: SUBCO with ST control; Initial_Board_Reference: MB1248; Path: ws/MCD_ApplicationBoards/Lists/MCDPARTSdatabase; Item Type: Item
U34 = MCD-00251: High power transient voltage suppressor, 7V breakdown; Part_Type: Diode; Manufacturer: STMICROELECTRONICS; BMS_Part_Number: 9179042; Provided_By: SUBCO with ST control; Initial_Board_Reference: MB1311; Path: ws/MCD_ApplicationBoards/Lists/MCDPARTSdatabase; Item Type: Item
U40 = MCD-00596: STM32F723IEK  (STM32F7) BGA176; Part_Type: IC; Manufacturer_Part_Number: STM32F723IEK6; Manufacturer: STMICROELECTRONICS; BMS_Part_Number: 9175300; Provided_By: SUBCO with ST control; Initial_Board_Reference: MB1331; Path: ws/MCD_ApplicationBoards/Lists/MCDPARTSdatabase; Item Type: Item
U45 = MCD-00136: Dual Transil array for ESD protection; Manufacturer: STMICROELECTRONICS; Part_Type: Diode; BMS_Part_Number: 9151112; Provided_By: SUBCO with ST control; Initial_Board_Reference: MB1262; Path: ws/MCD_ApplicationBoards/Lists/MCDPARTSdatabase; Item Type: Item
X1 = MCD-00597: Oscillator 25.00Mhz, -+50PPM, 3.3V, Temp -55 to +125°C; Manufacturer_Part_Number: NZ2520SB 25MHz END4869B; Manufacturer: NDK; Alternate_Manufacturer_Part_Number: KC2520B25.0000C10E00; Alternate_Manufacturer: AVX CORP/KYOCERA CORP; Part_Type: Crystal_Osc; BMS_Part_Number: 9157031; Provided_By: ST; Initial_Board_Reference: MB1331; Path: ws/MCD_ApplicationBoards/Lists/MCDPARTSdatabase; Item Type: Item

## Sheet ExtensionConnector.SchDoc: Extension Connectors
size A4; Date: Not used; ApprovedBy: Not used; CheckedBy: Not used; Author: Not used; CompanyName: STMicroelectronics; DrawnBy: Not used; Engineer: Not used; Organization: Not used; Address1: Not used; Address2: Not used; Address3: Not used; Address4: Not used; DocumentNumber: Not used; Revision: Not used; SheetNumber: 17; SheetTotal: 22
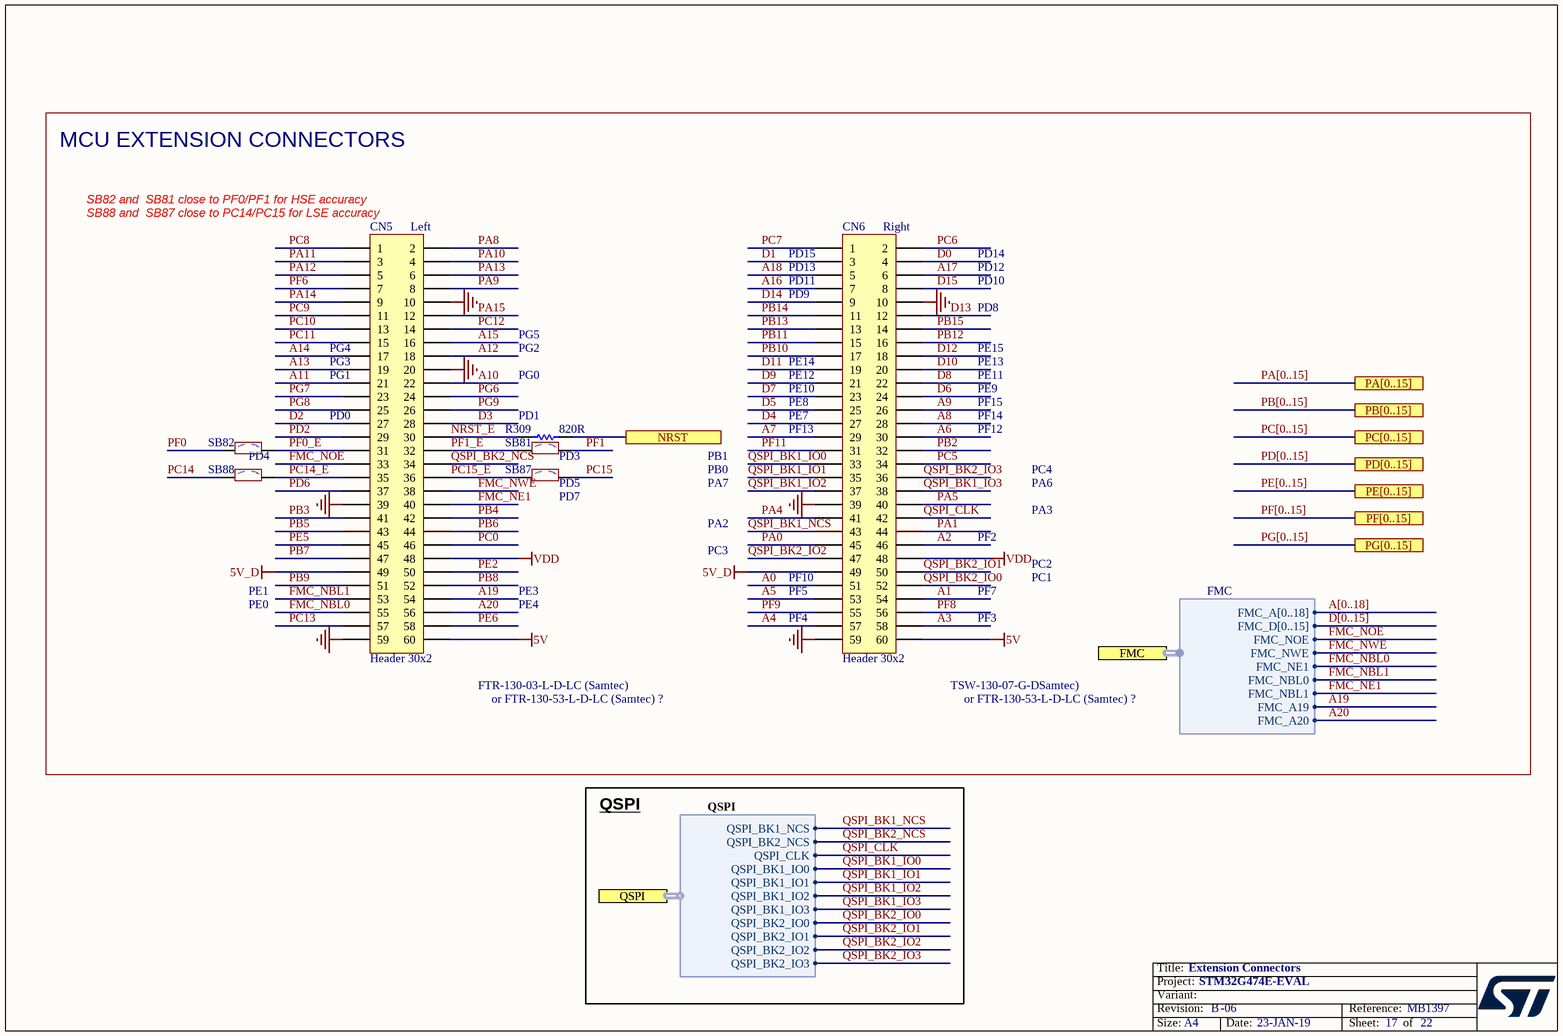
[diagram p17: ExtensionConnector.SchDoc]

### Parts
CN5  Header 30x2  [CON_SAMTEC_FTR-130-53-L-D-LC]
CN6  Header 30x2  [CON_SAMTEC_FTR-130-53-L-D-LC]
R309  value 820R  [R0402]  (hidden comment: Resistor)
SB81  SB_OFF  [SOLDER-BRIDGE_R0603-0R]  (value not drawn)
SB82  SB_OFF  [SOLDER-BRIDGE_R0603-0R]  (value not drawn)
SB87  SB_OFF  [SOLDER-BRIDGE_R0603-0R]  (value not drawn)
SB88  SB_OFF  [SOLDER-BRIDGE_R0603-0R]  (value not drawn)

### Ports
FMC (harness FMC), NRST, PA[0..15], PB[0..15], PC[0..15], PD[0..15], PE[0..15], PF[0..15], PG[0..15], QSPI (harness QSPI)

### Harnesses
FMC: FMC_NWE, FMC_NOE, FMC_NE1, FMC_A[0..18], FMC_D[0..15], FMC_NBL0, FMC_NBL1, FMC_A19, FMC_A20
QSPI: QSPI_BK1_IO1, QSPI_BK1_IO0, QSPI_CLK, QSPI_BK1_NCS, QSPI_BK1_IO2, QSPI_BK1_IO3, QSPI_BK2_IO1, QSPI_BK2_IO0, QSPI_BK2_IO2, QSPI_BK2_IO3, QSPI_BK2_NCS

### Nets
5V: CN5.60 CN6.60
5V_D: CN5.49 CN6.49
GND: CN5.10 CN5.20 CN5.39 CN5.59 CN6.10 CN6.39 CN6.59
VDD: CN5.48 CN6.48
A0: CN6.51
A1: CN6.54
A2: CN6.46
A3: CN6.58
A4: CN6.57
A5: CN6.53
A6: CN6.30
A7: CN6.29
A8: CN6.28
A9: CN6.26
A10: CN5.22
A11: CN5.21
A12: CN5.18
A13: CN5.19
A14: CN5.17
A15: CN5.16
A16: CN6.7
A17: CN6.6
A18: CN6.5
A19: CN5.54 ; port FMC.FMC_A19
A20: CN5.56 ; port FMC.FMC_A20
D0: CN6.4
D1: CN6.3
D2: CN5.27
D3: CN5.28
D4: CN6.27
D5: CN6.25
D6: CN6.24
D7: CN6.23
D8: CN6.22
D9: CN6.21
D10: CN6.20
D11: CN6.19
D12: CN6.18
D13: CN6.12
D14: CN6.9
D15: CN6.8
FMC_NBL0: CN5.55 ; port FMC.FMC_NE1
FMC_NBL1: CN5.53 ; port FMC.FMC_NBL0
FMC_NE1: CN5.40 ; port FMC.FMC_NBL1
FMC_NOE: CN5.33 ; port FMC.FMC_NOE
FMC_NWE: CN5.38 ; port FMC.FMC_NWE
NRST: R309.2 ; port NRST
NRST_E: CN5.30 R309.1
PA0: CN6.45
PA1: CN6.44
PA4: CN6.41
PA5: CN6.40
PA8: CN5.2
PA9: CN5.8
PA10: CN5.4
PA11: CN5.3
PA12: CN5.5
PA13: CN5.6
PA14: CN5.9
PA15: CN5.12
PB2: CN6.32
PB3: CN5.41
PB4: CN5.42
PB5: CN5.43
PB6: CN5.44
PB7: CN5.47
PB8: CN5.52
PB9: CN5.51
PB10: CN6.17
PB11: CN6.15
PB12: CN6.16
PB13: CN6.13
PB14: CN6.11
PB15: CN6.14
PC0: CN5.46
PC5: CN6.34
PC6: CN6.2
PC7: CN6.1
PC8: CN5.1
PC9: CN5.11
PC10: CN5.13
PC11: CN5.15
PC12: CN5.14
PC13: CN5.57
PC14: SB88.1
PC14_E: CN5.35 SB88.2
PC15: SB87.2
PC15_E: CN5.36 SB87.1
PD2: CN5.29
PD6: CN5.37
PE2: CN5.50
PE5: CN5.45
PE6: CN5.58
PF0: SB82.1
PF0_E: CN5.31 SB82.2
PF1: SB81.2
PF1_E: CN5.32 SB81.1
PF6: CN5.7
PF8: CN6.56
PF9: CN6.55
PF11: CN6.31
PG6: CN5.24
PG7: CN5.23
PG8: CN5.25
PG9: CN5.26
QSPI_BK1_IO0: CN6.33 ; port QSPI.QSPI_BK1_IO0
QSPI_BK1_IO1: CN6.35 ; port QSPI.QSPI_BK1_IO1
QSPI_BK1_IO2: CN6.37 ; port QSPI.QSPI_BK1_IO2
QSPI_BK1_IO3: CN6.38 ; port QSPI.QSPI_BK1_IO3
QSPI_BK1_NCS: CN6.43 ; port QSPI.QSPI_BK1_NCS
QSPI_BK2_IO0: CN6.52 ; port QSPI.QSPI_BK2_IO0
QSPI_BK2_IO1: CN6.50 ; port QSPI.QSPI_BK2_IO1
QSPI_BK2_IO2: CN6.47 ; port QSPI.QSPI_BK2_IO2
QSPI_BK2_IO3: CN6.36 ; port QSPI.QSPI_BK2_IO3
QSPI_BK2_NCS: CN5.34 ; port QSPI.QSPI_BK2_NCS
QSPI_CLK: CN6.42 ; port QSPI.QSPI_CLK

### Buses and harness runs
bus A[0..18]
bus D[0..15]
bus PA[0..15] = port PA[0..15]
bus PB[0..15] = port PB[0..15]
bus PC[0..15] = port PC[0..15]
bus PD[0..15] = port PD[0..15]
bus PE[0..15] = port PE[0..15]
bus PF[0..15] = port PF[0..15]
bus PG[0..15] = port PG[0..15]

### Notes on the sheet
- MCU EXTENSION CONNECTORS
- (near CN5) SB82 and  SB81 close to PF0/PF1 for HSE accuracy
- (near CN5) SB88 and  SB87 close to PC14/PC15 for LSE accuracy
- (near CN5) Left
- (near CN6) Right
- (near CN6) PD9
- (near CN6) PD11
- (near CN6) PD13
- (near CN6) PD15
- PD8
- PD10
- PD12
- PD14
- (near CN5) PG1
- (near CN5) PG3
- (near CN5) PG4
- PG0
- PG2
- PG5
- (near CN6) PE12
- (near CN6) PE14
- PE11
- PE13
- PE15
- (near CN5) PD0
- (near R309) PD1
- (near CN6) PE8
- (near CN6) PE10
- (near CN6) PF13
- (near CN6) PE7
- PE9
- PF12
- PF14
- PF15
- (near SB82) PD4
- (near SB87) PD5
- (near SB87) PD7
- (near SB81) PD3
- PB0
- PB1
- PA7
- PC4
- PA3
- PA6
- PC3
- PA2
- (near CN6) PF10
- PF2
- PC1
- PC2
- PE0
- PE1
- PE3
- PE4
- (near CN6) PF4
- (near CN6) PF5
- PF3
- PF7
- (near CN5) FTR-130-03-L-D-LC (Samtec)
- or FTR-130-53-L-D-LC (Samtec) ?
- (near CN6) TSW-130-07-G-DSamtec)
- QSPI

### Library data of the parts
CN5 CN6 = MCD-00576: Header 30x2, 1.27mm, VR, CMS, Height 7.24mm; Part_Type: Connector; Manufacturer_Part_Number: FTR-130-53-L-D-LC; Manufacturer: SAMTEC; Alternate_Manufacturer_Part_Number: P1039-2*30MGF-089-1A; Alternate_Manufacturer: JIUBABA; Provided_By: SUBCO; Initial_Board_Reference: MB1331; Path: ws/MCD_ApplicationBoards/Lists/MCDPARTSdatabase; Item Type: Item
R309 = MCD-00527: as R221 on sheet STLink_V3E_SWD
SB81 SB82 SB87 SB88 = MCD-00072: Solder Bridge OFF; Part_Type: Mechanical; Manufacturer_Part_Number: RC0603JR-070RL; Manufacturer: YAGEO; Provided_By: SUBCO; Initial_Board_Reference: MB1274; Path: ws/MCD_ApplicationBoards/Lists/MCDPARTSdatabase; Item Type: Item

## Sheet USB_PD.SchDoc: USB_PD
size A4; Date: Not used; ApprovedBy: Not used; CheckedBy: Not used; Author: Not used; CompanyName: STMicroelectronics; DrawnBy: Not used; Engineer: Not used; Organization: Not used; Address1: Not used; Address2: Not used; Address3: Not used; Address4: Not used; DocumentNumber: Not used; Revision: Not used; SheetNumber: 5; SheetTotal: 22
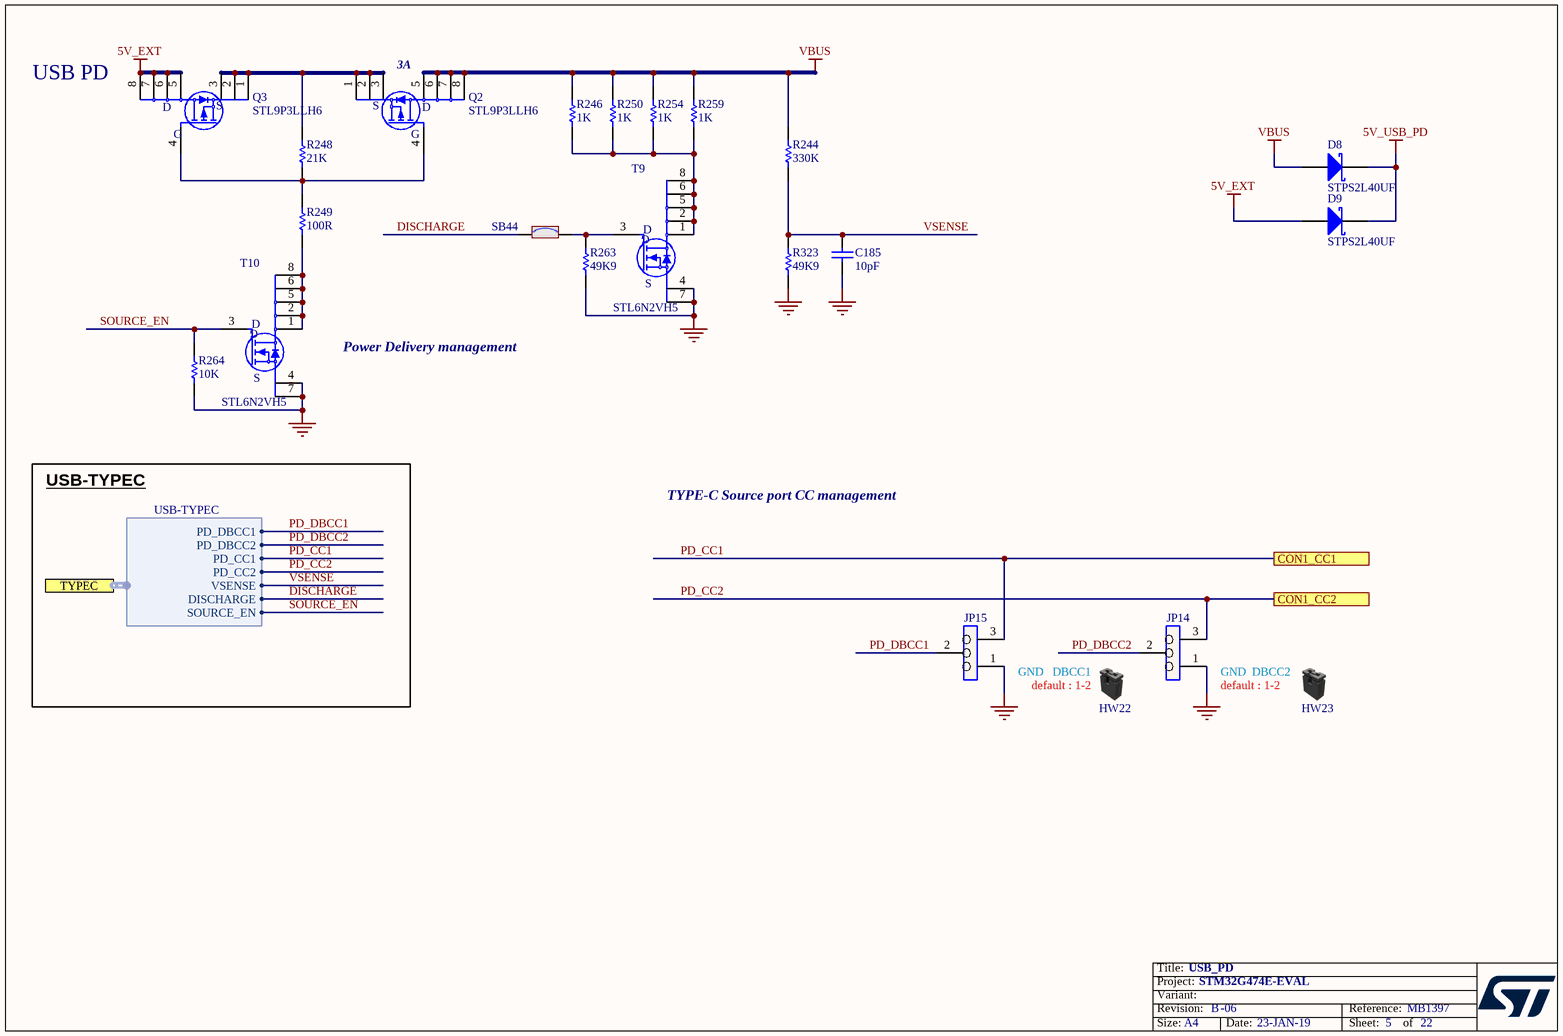
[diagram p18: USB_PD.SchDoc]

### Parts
C185  value 10pF  [C0603]  (hidden comment: Capacitor)
D8  STPS2L40UF  [DIO_SMB-FLAT_1A_2K]
D9  STPS2L40UF  [DIO_SMB-FLAT_1A_2K]
HW22  Shunt Black 2.54mm  (value not drawn)  (mechanical)
HW23  Shunt Black 2.54mm  (value not drawn)  (mechanical)
JP14  Jumper_Header 3x1  [CON_SAMTEC_TSW-103-07-F-S]  (value not drawn)
JP15  Jumper_Header 3x1  [CON_SAMTEC_TSW-103-07-F-S]  (value not drawn)
Q2  STL9P3LLH6  [MOS_POWERFLAT_3P3X3P3_P065]
Q3  STL9P3LLH6  [MOS_POWERFLAT_3P3X3P3_P065]
R244  value 330K  [R0603]  (hidden comment: Resistor)
R246  value 1K  [R0603]  (hidden comment: Resistor)
R248  value 21K  [R0603]  (hidden comment: Resistor)
R249  value 100R  [R0603]  (hidden comment: Resistor)
R250  value 1K  [R0603]  (hidden comment: Resistor)
R254  value 1K  [R0603]  (hidden comment: Resistor)
R259  value 1K  [R0603]  (hidden comment: Resistor)
R263  value 49K9  [R0603]  (hidden comment: Resistor)
R264  value 10K  [R0603]  (hidden comment: Resistor)
R323  value 49K9  [R0603]  (hidden comment: Resistor)
SB44  SB_ON  [SOLDER-BRIDGE_R0603-0R]  (value not drawn)
T9  STL6N2VH5  [MOS_POWERFLAT_2X2_P065]
T10  STL6N2VH5  [MOS_POWERFLAT_2X2_P065]

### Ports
CON1_CC1, CON1_CC2, TYPEC (harness USB-TYPEC)

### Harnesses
USB-TYPEC: PD_DBCC1, PD_DBCC2, PD_CC1, PD_CC2, VSENSE, DISCHARGE, SOURCE_EN

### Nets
5V_EXT: D9.1(A) Q3.5(D) Q3.6(D) Q3.7(D) Q3.8(D)
5V_USB_PD: D8.2(K) D9.2(K)
GND: C185.1 JP14.1 JP15.1 R263.1 R264.1 R323.1 T9.4(S) T9.7(S) T10.4(S) T10.7(S)
VBUS: D8.1(A) Q2.5(D) Q2.6(D) Q2.7(D) Q2.8(D) R244.2 R246.2 R250.2 R254.2 R259.2
DISCHARGE: SB44.1 ; port TYPEC.DISCHARGE
PD_CC1: JP15.3 ; port CON1_CC1, port TYPEC.PD_CC1  [project net CON1_CC1]
PD_CC2: JP14.3 ; port CON1_CC2, port TYPEC.PD_CC2  [project net CON1_CC2]
PD_DBCC1: JP15.2 ; port TYPEC.PD_DBCC1
PD_DBCC2: JP14.2 ; port TYPEC.PD_DBCC2
SOURCE_EN: R264.2 T10.3(G) ; port TYPEC.SOURCE_EN
VSENSE: C185.2 R244.1 R323.2 ; port TYPEC.VSENSE
NetQ2_1: Q2.1(S) Q2.2(S) Q2.3(S) Q3.1(S) Q3.2(S) Q3.3(S) R248.2
NetQ2_4: Q2.4(G) Q3.4(G) R248.1 R249.2
NetR246_1: R246.1 R250.1 R254.1 R259.1 T9.1(D) T9.2(D) T9.5(D) T9.6(D) T9.8(D)
NetR249_1: R249.1 T10.1(D) T10.2(D) T10.5(D) T10.6(D) T10.8(D)
NetR263_2: R263.2 SB44.2 T9.3(G)

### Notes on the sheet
- (near Q3) USB PD
- (near Q2) 3A
- Power Delivery management
- USB-TYPEC
- TYPE-C Source port CC management
- (near HW22) GND   DBCC1
- (near HW22) default : 1-2
- (near HW23) default : 1-2
- (near HW23) GND  DBCC2

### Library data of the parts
C185 = MCD-00637: Capacitor, MLCC, 10pF, 50V, NPO, 5%, 0603, T=0,8mm; Manufacturer_Part_Number: CC0603JRNPO9BN100; Manufacturer: YAGEO; Provided_By: SUBCO; Initial_Board_Reference: MB1319; Path: ws/MCD_ApplicationBoards/Lists/MCDPARTSdatabase; Item Type: Item
D8 D9 = MCD-01087: Low drop power Schottky rectifier(2A, 40V, 0.34V); Part_Type: Diode; Manufacturer: STMICROELECTRONICS; BMS_Part_Number: 9151009; Provided_By: SUBCO with ST control; Initial_Board_Reference: MB1381; Remark: Anode = pin 1; Path: ws/MCD_ApplicationBoards/Lists/MCDPARTSdatabase; Item Type: Item
HW22 HW23 = MCD-00043: SHUNT 2.54mm BLACK; Part_Type: Mechanical; Manufacturer_Part_Number: SNT-100-BK-G; Manufacturer: SAMTEC; Provided_By: SUBCO; Initial_Board_Reference: MB1274; Value: SNT-100-BK-G; Path: ws/MCD_ApplicationBoards/Lists/MCDPARTSdatabase; Item Type: Item
JP14 JP15 = MCD-00111: Header, 3x1, 2,54mm, VR, TH, Height 5.84mm/2.54mm; Part_Type: Connector; Manufacturer_Part_Number: TSW-103-07-F-S; Manufacturer: SAMTEC; Provided_By: SUBCO; Initial_Board_Reference: MB1262; Path: ws/MCD_ApplicationBoards/Lists/MCDPARTSdatabase; Item Type: Item
Q2 Q3 = MCD-01126: Power Mosfet, P-channel,VDS -30V,RDS 12mohm typ,ID -9A; Part_Type: IC; Manufacturer: STMICROELECTRONICS; Provided_By: SUBCO with ST control; Initial_Board_Reference: MB1272; Remark: footprint MOS_POWERFLAT_3P3X3P3_P065 pin 5-8 for solder mask and paste mask profile is same as top layer; Path: ws/MCD_ApplicationBoards/Lists/MCDPARTSdatabase; Item Type: Item
R244 = MCD-00458: Resistor,330K,0603,1%,1/10W; Manufacturer_Part_Number: RC0603FR-07330KL; Manufacturer: YAGEO; Provided_By: SUBCO; Initial_Board_Reference: MBxxxx; Path: ws/MCD_ApplicationBoards/Lists/MCDPARTSdatabase; Item Type: Item
R246 R250 R254 R259 = MCD-00070: Resistor,1K,0603,1%,1/10W; Manufacturer_Part_Number: RC0603FR-071KL; Manufacturer: YAGEO; Provided_By: SUBCO; Initial_Board_Reference: MB1274; Path: ws/MCD_ApplicationBoards/Lists/MCDPARTSdatabase; Item Type: Item
R248 = MCD-01189: Resistor,21K,0603,1%,1/10W; Manufacturer_Part_Number: RC0603FR-0721KL; Manufacturer: YAGEO; Provided_By: SUBCO; Initial_Board_Reference: MB1397; Path: ws/MCD_ApplicationBoards/Lists/MCDPARTSdatabase; Item Type: Item
R249 = MCD-00224: Resistor,100R,0603,1%,1/10W; Manufacturer_Part_Number: RC0603FR-07100RL; Manufacturer: YAGEO; Provided_By: SUBCO; Initial_Board_Reference: MB1319; Path: ws/MCD_ApplicationBoards/Lists/MCDPARTSdatabase; Item Type: Item
R263 R323 = MCD-01171: Resistor,49K9,0603,1%; Manufacturer_Part_Number: RC0603FR-0749K9L; Manufacturer: YAGEO; Provided_By: SUBCO; Initial_Board_Reference: MB1397; Path: ws/MCD_ApplicationBoards/Lists/MCDPARTSdatabase; Item Type: Item
R264 = MCD-00220: as R176 on sheet Peripherals
SB44 = MCD-00071: as SB1 on sheet Peripherals
T9 T10 = MCD-01028: as T1 on sheet Peripherals

## Sheet Debug_connector.SchDoc: Debug connector
size A4; Date: Not used; ApprovedBy: Not used; CheckedBy: Not used; Author: Not used; CompanyName: STMicroelectronics; DrawnBy: Not used; Engineer: Not used; Organization: Not used; Address1: Not used; Address2: Not used; Address3: Not used; Address4: Not used; DocumentNumber: Not used; Revision: Not used; SheetNumber: 18; SheetTotal: 22
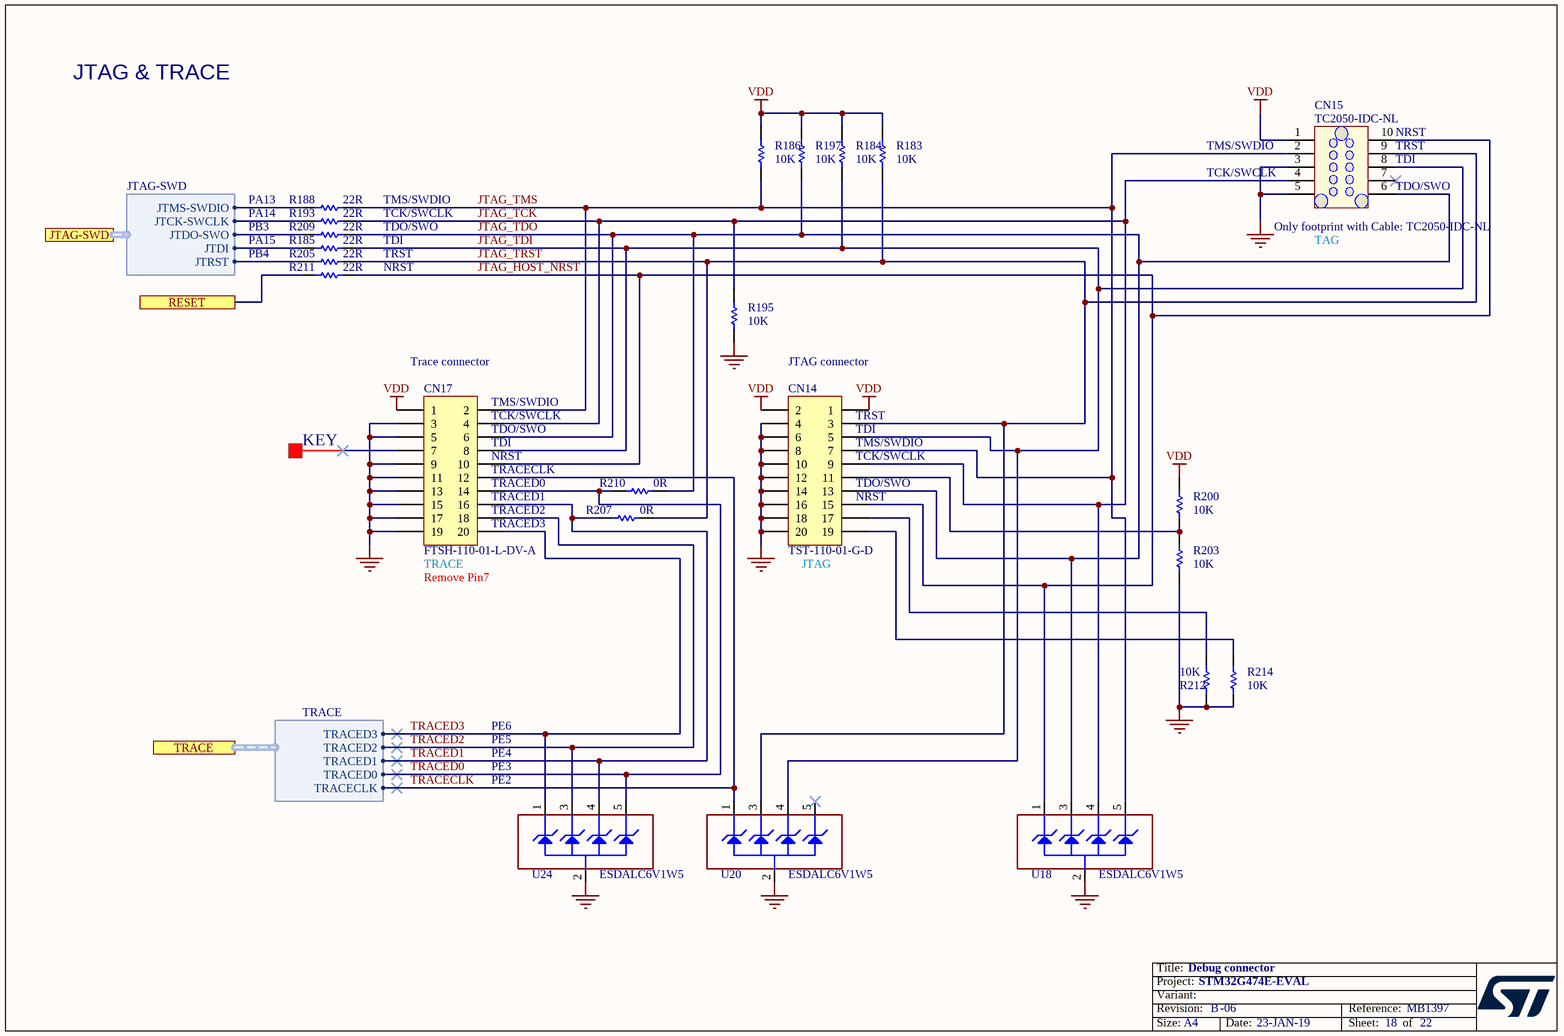
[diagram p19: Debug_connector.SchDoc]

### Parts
CN14  value TST-110-01-G-D  [CON_CVILUX_CH87-20-2-V-1-00]  (hidden comment: Header 10x2)
CN15  value TC2050-IDC-NL  [CON_TAG-C_TC2050-IDC-NL]  (hidden comment: Tag-10-C)
CN17  value FTSH-110-01-L-DV-A  [CON_SAMTEC_FTSH-110-01-L-DV-A]  (hidden comment: Header 10x2)
R183  value 10K  [R0402]  (hidden comment: Resistor)
R184  value 10K  [R0402]  (hidden comment: Resistor)
R185  value 22R  [R0402]  (hidden comment: Resistor)
R186  value 10K  [R0402]  (hidden comment: Resistor)
R188  value 22R  [R0402]  (hidden comment: Resistor)
R193  value 22R  [R0402]  (hidden comment: Resistor)
R195  value 10K  [R0402]  (hidden comment: Resistor)
R197  value 10K  [R0402]  (hidden comment: Resistor)
R200  value 10K  [R0402]  (hidden comment: Resistor)
R203  value 10K  [R0402]  (hidden comment: Resistor)
R205  value 22R  [R0402]  (hidden comment: Resistor)
R207  value 0R  [R0402]  (hidden comment: Resistor)
R209  value 22R  [R0402]  (hidden comment: Resistor)
R210  value 0R  [R0402]  (hidden comment: Resistor)
R211  value 22R  [R0402]  (hidden comment: Resistor)
R212  value 10K  [R0402]  (hidden comment: Resistor)
R214  value 10K  [R0402]  (hidden comment: Resistor)
U18  ESDALC6V1W5  [ESD_SOT323-5L]
U20  ESDALC6V1W5  [ESD_SOT323-5L]
U24  ESDALC6V1W5  [ESD_SOT323-5L]

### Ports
JTAG-SWD (harness JTAG-SWD), RESET, TRACE (harness TRACE)

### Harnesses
TRACE: TRACECLK, TRACED0, TRACED1, TRACED2, TRACED3
JTAG-SWD: JTMS-SWDIO, JTCK-SWCLK, JTDI, JTDO-SWO, JTRST

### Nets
GND: CN14.4 CN14.6 CN14.8 CN14.10 CN14.12 CN14.14 CN14.16 CN14.18 CN14.20 CN15.3 CN15.5 CN17.3 CN17.5 CN17.9 CN17.11 CN17.13 CN17.15 CN17.17 CN17.19 R195.1 R203.1 R212.1 R214.1 U18.2(GND) U20.2(GND) U24.2(GND)
VDD: CN14.1 CN14.2 CN15.1 CN17.1 R183.2 R184.2 R186.2 R197.2 R200.2
JTAG_HOST_NRST: CN14.15 CN15.10 CN17.10 R211.1 U18.1(IO1)
JTAG_TCK: CN14.9 CN15.4 CN17.4 R193.1 R195.2 U18.4(IO3)
JTAG_TDI: CN14.5 CN15.8 CN17.8 R184.1 R185.1 U20.4(IO3)
JTAG_TDO: CN14.13 CN15.6 CN17.6 R197.1 R209.1 R210.2 U18.3(IO2)
JTAG_TMS: CN14.7 CN15.2 CN17.2 R186.1 R188.1 U18.5(IO4)
JTAG_TRST: CN14.3 CN15.9 R183.1 R205.1 R207.2 U20.3(IO2)
JTCK-SWCLK: R193.2 ; port JTAG-SWD.JTCK-SWCLK
JTDI: R185.2 ; port JTAG-SWD.JTDI
JTDO-SWO: R209.2 ; port JTAG-SWD.JTDO-SWO
JTMS-SWDIO: R188.2 ; port JTAG-SWD.JTMS-SWDIO
JTRST: R205.2 ; port JTAG-SWD.JTRST
TRACECLK: CN17.12 U20.1(IO1) ; port TRACE.TRACECLK
TRACED0: CN17.14 R210.1 U24.5(IO4) ; port TRACE.TRACED0
TRACED1: CN17.16 R207.1 U24.4(IO3) ; port TRACE.TRACED1
TRACED2: CN17.18 U24.3(IO2) ; port TRACE.TRACED2
TRACED3: CN17.20 U24.1(IO1) ; port TRACE.TRACED3
NetCN14_11: CN14.11 R200.1 R203.2
NetCN14_17: CN14.17 R212.2
NetCN14_19: CN14.19 R214.2
NetR211_2: R211.2 ; port RESET

Not connected (* = marked no-connect by the designer): CN15 7*; CN17 7*; U20 5(IO4)*

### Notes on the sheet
- JTAG & TRACE
- (near CN15) TMS/SWDIO
- (near CN15) TCK/SWCLK
- (near CN15) TDI
- (near CN15) NRST
- (near CN15) TRST
- PA13
- PA14
- PB3
- PA15
- TMS/SWDIO
- TCK/SWCLK
- TDO/SWO
- TDI
- (near CN15) Only footprint with Cable: TC2050-IDC-NL
- (near CN15) TAG
- (near CN15) TDO/SWO
- PB4
- TRST
- NRST
- (near CN17) Trace connector
- JTAG connector
- KEY
- (near CN17) TMS/SWDIO
- (near CN17) TCK/SWCLK
- (near CN17) TDO/SWO
- (near CN17) TDI
- (near CN14) TRST
- (near CN14) TDI
- (near CN14) TMS/SWDIO
- (near CN17) NRST
- (near CN17) TRACECLK
- (near CN17) TRACED0
- (near CN17) TRACED1
- (near CN17) TRACED2
- (near CN14) TCK/SWCLK
- (near CN14) TDO/SWO
- (near CN14) NRST
- (near CN17) Remove Pin7
- (near CN17) TRACE
- (near CN17) TRACED3
- (near CN14) JTAG
- PE6
- PE5
- PE4
- PE3
- (near U24) PE2

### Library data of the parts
CN14 = MCD-01058: Header, 2.54mm, 10x2, VR, TH, Height 9.1mm/3,1mm; Part_Type: Connector; Manufacturer: SAMTEC; Alternate_Manufacturer_Part_Number: CH87-20-2-V-1-00; Alternate_Manufacturer: CVILUX; Provided_By: SUBCO; Initial_Board_Reference: MB1331; Path: ws/MCD_ApplicationBoards/Lists/MCDPARTSdatabase; Item Type: Item
CN15 = MCD-00031: Tag_Connector Header, 10x2, No legs; Manufacturer_Part_Number: TC2050-IDC-NL-FP; Manufacturer: TAG-CONNECT LLC; Provided_By: SUBCO; Initial_Board_Reference: MB1274; Path: ws/MCD_ApplicationBoards/Lists/MCDPARTSdatabase; Item Type: Item
CN17 = MCD-01561: Header 10x2, 1.27mm, VR, CMS, Height 3.05mm with alignment pin; Part_Type: Connector; Manufacturer: SAMTEC; Provided_By: SUBCO; Initial_Board_Reference: MB1397; Path: ws/MCD_ApplicationBoards/Lists/MCDPARTSdatabase; Item Type: Item; Remark: new part FTSH-110-01-L-DV-A to replace MCD-00557 footprint
R183 R184 R186 R195 R197 R200 R203 R212 R214 = MCD-00053: as R294 on sheet Peripherals
R185 R188 R193 R205 R209 R211 = MCD-00189: as R189 on sheet STLink_V3E_SWD
R207 R210 = MCD-00052: as R1 on sheet Peripherals
U18 U20 U24 = MCD-00136: as U45 on sheet STLink_V3E_SWD

## Sheet RS232&RS485.SchDoc: RS232 & RS485
size A4; Date: Not used; ApprovedBy: Not used; CheckedBy: Not used; Author: Not used; CompanyName: STMicroelectronics; DrawnBy: Not used; Engineer: Not used; Organization: Not used; Address1: Not used; Address2: Not used; Address3: Not used; Address4: Not used; DocumentNumber: Not used; Revision: Not used; SheetNumber: 11; SheetTotal: 22
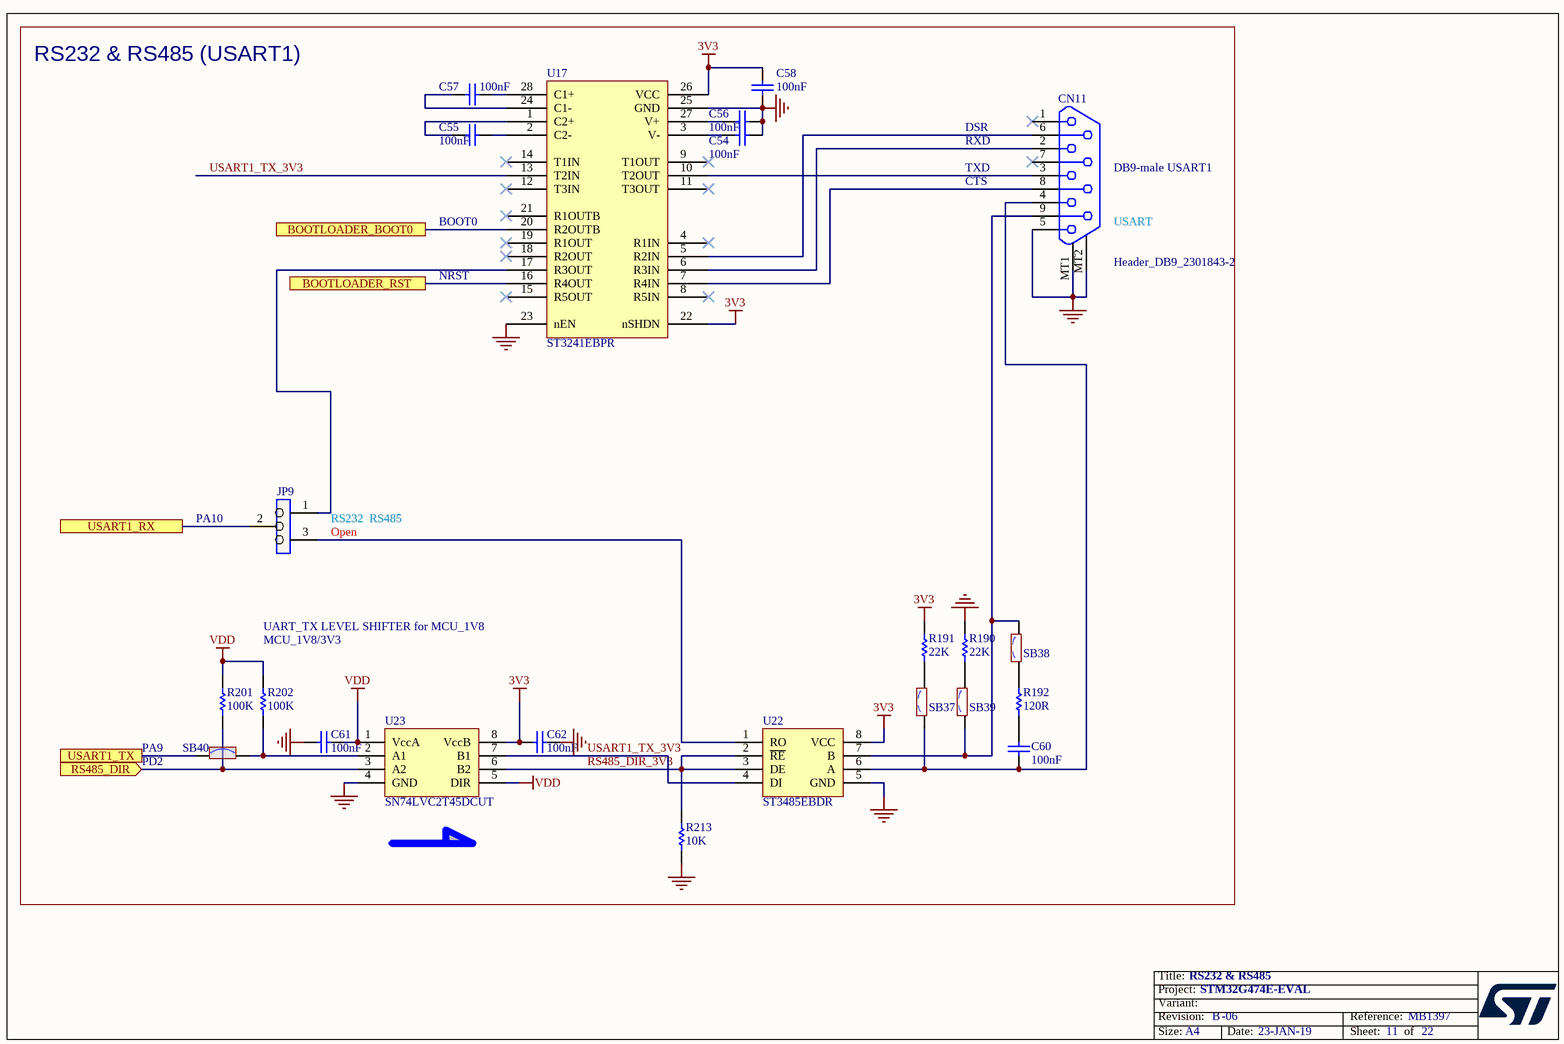
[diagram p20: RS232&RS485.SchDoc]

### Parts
C54  value 100nF  [C0402]  (hidden comment: Capacitor)
C55  value 100nF  [C0402]  (hidden comment: Capacitor)
C56  value 100nF  [C0402]  (hidden comment: Capacitor)
C57  value 100nF  [C0402]  (hidden comment: Capacitor)
C58  value 100nF  [C0402]  (hidden comment: Capacitor)
C60  value 100nF  [C0603]  (hidden comment: Capacitor)
C61  value 100nF  [C0603]  (hidden comment: Capacitor)
C62  value 100nF  [C0603]  (hidden comment: Capacitor)
CN11  value Header_DB9_2301843-2  [CON_DB9-MALE_TYCO_2301843-2]  (hidden comment: DB9_Header_male_2301843-2)
JP9  Jumper_Header 3x1  [CON_SAMTEC_TSW-103-07-F-S]  (value not drawn)
R190  value 22K  [R0603]  (hidden comment: Resistor)
R191  value 22K  [R0603]  (hidden comment: Resistor)
R192  value 120R  [R0603]  (hidden comment: Resistor)
R201  value 100K  [R0603]  (hidden comment: Resistor)
R202  value 100K  [R0603]  (hidden comment: Resistor)
R213  value 10K  [R0603]  (hidden comment: Resistor)
SB37  SB_OFF  [SOLDER-BRIDGE_R0603-0R]  (value not drawn)
SB38  SB_OFF  [SOLDER-BRIDGE_R0603-0R]  (value not drawn)
SB39  SB_OFF  [SOLDER-BRIDGE_R0603-0R]  (value not drawn)
SB40  SB_ON  [SOLDER-BRIDGE_R0603-0R]  (value not drawn)
U17  ST3241EBPR  [ICC_SSOP28_10P2X5P3_P065]
U22  ST3485EBDR  [ICC_SO8_5X4_P127]
U23  SN74LVC2T45DCUT  [ICC_VSSOP8_DCU_R-PDSO-G8_2X2P30_P050]

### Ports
BOOTLOADER_BOOT0, BOOTLOADER_RST, RS485_DIR (in), USART1_RX, USART1_TX

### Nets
3V3: C58.1 C62.2 R191.1 U17.22(nSHDN) U17.26(VCC) U22.8(VCC) U23.8(VccB)
GND: C54.1 C56.1 C58.2 C61.2 C62.1 CN11.5 CN11.MT1 CN11.MT2 R190.2 R213.1 U17.23(nEN) U17.25(GND) U22.5(GND) U23.4(GND)
VDD: C61.1 R201.2 R202.2 U23.1(VccA) U23.5(DIR)
RS485_DIR: R201.1 U23.3(A2) ; port RS485_DIR
RS485_DIR_3V3: R213.2 U22.2(~{RE}) U22.3(DE) U23.6(B2)
USART1_RX: JP9.2 ; port USART1_RX
USART1_TX: SB40.1 ; port USART1_TX
USART1_TX_3V3: U17.13(T2IN) U22.4(DI) U23.7(B1)
NetC54_2: C54.2 U17.3(V-)
NetC55_1: C55.1 U17.1(C2+)
NetC55_2: C55.2 U17.2(C2-)
NetC56_2: C56.2 U17.27(V+)
NetC57_1: C57.1 U17.24(C1-)
NetC57_2: C57.2 U17.28(C1+)
NetC60_1: C60.1 CN11.4 SB37.1 U22.6(A)
NetC60_2: C60.2 R192.1
NetCN11_2: CN11.2 U17.6(R3IN)
NetCN11_3: CN11.3 U17.10(T2OUT)
NetCN11_6: CN11.6 U17.5(R2IN)
NetCN11_8: CN11.8 U17.7(R4IN)
NetCN11_9: CN11.9 SB38.2 SB39.1 U22.7(B)
NetD2_1: U17.20(R2OUTB) ; port BOOTLOADER_BOOT0
NetJP9_1: JP9.1 U17.17(R3OUT)
NetJP9_3: JP9.3 U22.1(RO)
NetJP18_2: U17.16(R4OUT) ; port BOOTLOADER_RST
NetR190_1: R190.1 SB39.2
NetR191_2: R191.2 SB37.2
NetR192_2: R192.2 SB38.1
NetR202_1: R202.1 SB40.2 U23.2(A1)

Not connected (* = marked no-connect by the designer): CN11 1* 7*; U17 4(R1IN)* 8(R5IN)* 9(T1OUT)* 11(T3OUT)* 12(T3IN)* 14(T1IN)* 15(R5OUT)* 18(R2OUT)* 19(R1OUT)* 21(R1OUTB)*

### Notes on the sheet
- RS232 & RS485 (USART1)
- RXD
- TXD
- CTS
- DSR
- (near CN11) DB9-male USART1
- BOOT0
- (near CN11) USART
- NRST
- PA10
- (near JP9) RS232  RS485
- (near JP9) Open
- UART_TX LEVEL SHIFTER for MCU_1V8
- MCU_1V8/3V3
- PA9
- PD2

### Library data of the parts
C54-C58 = MCD-00006: as C157 on sheet Peripherals
C60-C62 = MCD-00211: as C13 on sheet Peripherals
CN11 = MCD-01978: Connector_DB9-Male, 9pins, 1.39mm, RA, TH, T= 13.575mm/3.8mm; Part_Preference: Recommended; Manufacturer: TE CONNECTIVITY; Component_Country_Of_Origin: China; ShowFields: YES; ID: 4078
JP9 = MCD-00111: as JP14 on sheet USB_PD
R190 R191 = MCD-00430: Resistor,22K,0603,1%,1/10W; Manufacturer_Part_Number: RC0603FR-0722KL; Manufacturer: YAGEO; Provided_By: SUBCO; Initial_Board_Reference: MBxxxx; Path: ws/MCD_ApplicationBoards/Lists/MCDPARTSdatabase; Item Type: Item
R192 = MCD-00338: Resistor,120R,0603,1%,1/10W; Manufacturer_Part_Number: RC0603FR-07120RL; Manufacturer: YAGEO; BMS_Part_Number: 9129734; Provided_By: SUBCO; Initial_Board_Reference: MBxxxx; Path: ws/MCD_ApplicationBoards/Lists/MCDPARTSdatabase; Item Type: Item
R201 R202 = MCD-00223: as R215 on sheet STLink_V3E_SWD
R213 = MCD-00220: as R176 on sheet Peripherals
SB37-SB39 = MCD-00072: as SB81 on sheet ExtensionConnector
SB40 = MCD-00071: as SB1 on sheet Peripherals
U17 = MCD-00152: RS-232 transceiver with auto-power-down; Part_Type: IC; Manufacturer: STMICROELECTRONICS; BMS_Part_Number: 9176312; Provided_By: SUBCO with ST control; Initial_Board_Reference: MB1262; Path: ws/MCD_ApplicationBoards/Lists/MCDPARTSdatabase; Item Type: Item
U22 = MCD-01160: RS-485/RS-422 transceiver Up to 12Mbps; Part_Type: IC; Manufacturer: STMICROELECTRONICS; BMS_Part_Number: 9172020; Provided_By: SUBCO with ST control
U23 = MCD-00264: Dual bit dual supply bus transceiver; Part_Type: IC; Manufacturer: TEXAS INSTRUMENTS; Provided_By: SUBCO; Initial_Board_Reference: MB1319; Path: ws/MCD_ApplicationBoards/Lists/MCDPARTSdatabase; Item Type: Item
